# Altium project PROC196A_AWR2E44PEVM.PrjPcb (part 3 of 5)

## Sheet PROC196A_Ethernet_PHY.SchDoc
size 431 x 279 mm; Date: Not shown in title block; ApprovedBy: Not shown in title block; CheckedBy: Not shown in title block; Author: Not shown in title block; CompanyName: Not shown in title block; Engineer: Not shown in title block; Organization: Not shown in title block; Address1: Not shown in title block; Address2: Not shown in title block; Address3: Not shown in title block; Address4: Not shown in title block; DocumentNumber: 12; Revision: Use project parameter SCH_Rev; SheetNumber: 12; SheetTotal: 25; PageSetup: Record=PageOptions¦CenterHorizontal=True¦CenterVertical=True¦PrintScale=1.00¦XCorrection=1.00¦YCorrection=1.00¦PrintKind=0¦BorderSize=5000000¦LeftOffset=0¦BottomOffset=0¦Orientation=2¦PaperLength=1000¦PaperWidth=1000¦Scale=100¦PaperSource=15¦PrintQuality=600¦MediaType=1¦DitherType=10¦PaperKind=Letter¦PrintScaleMode=1
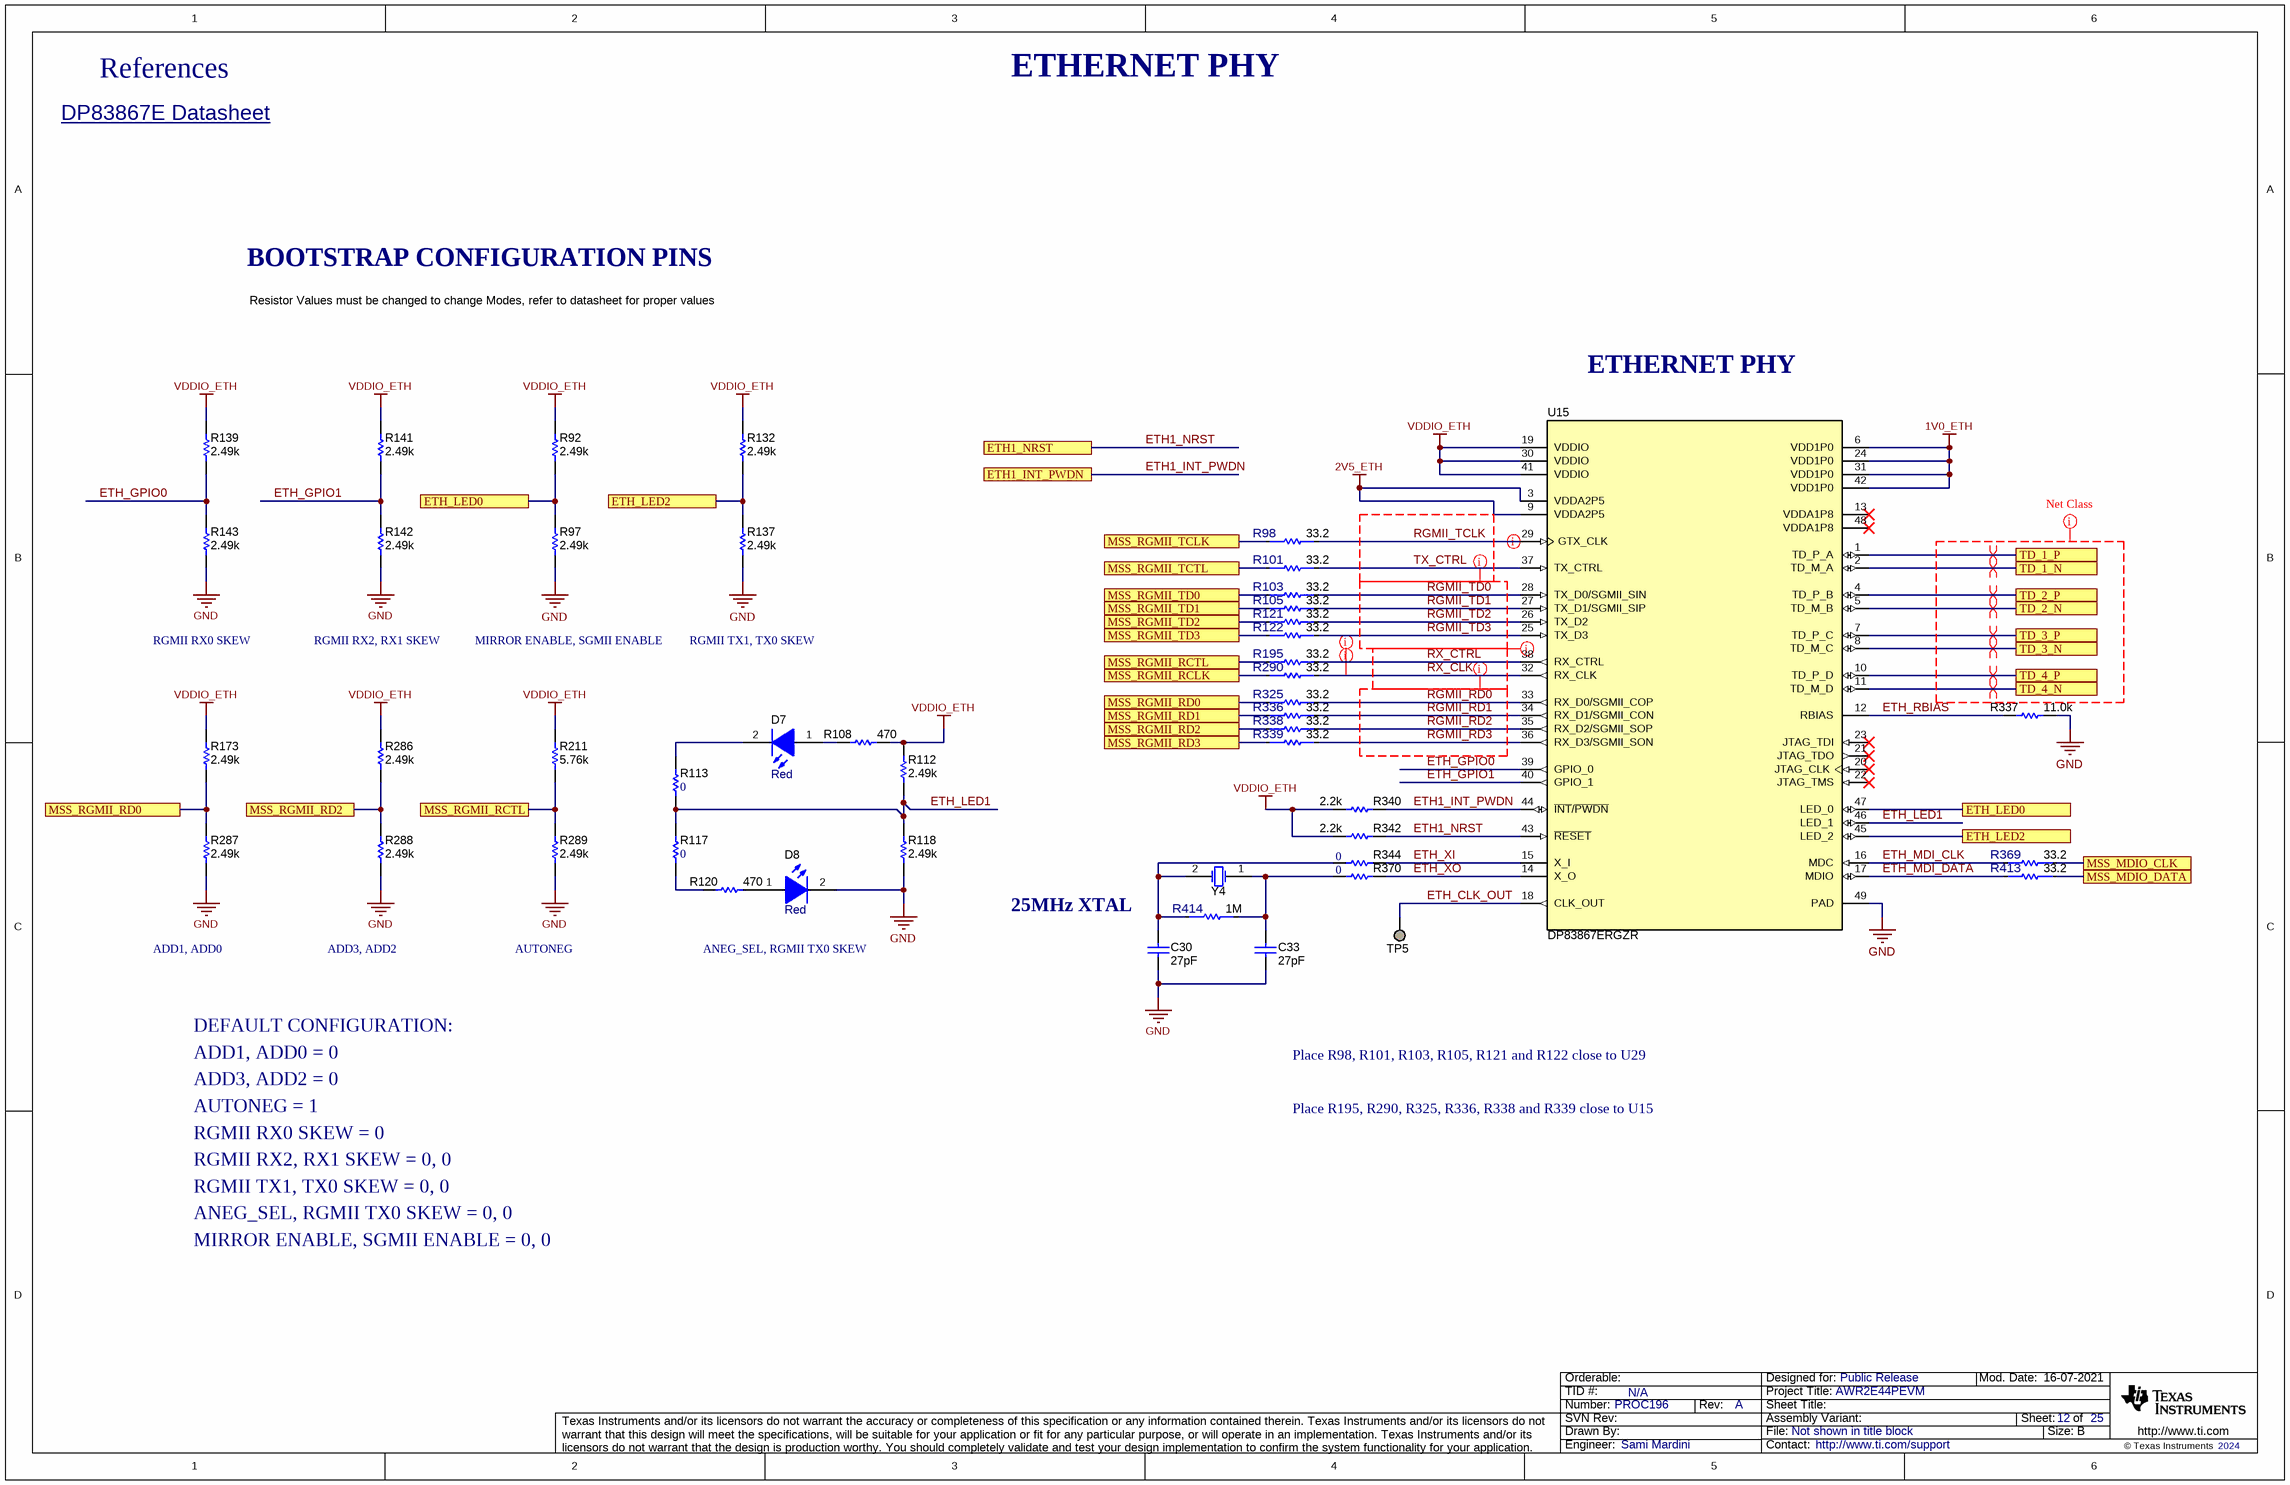
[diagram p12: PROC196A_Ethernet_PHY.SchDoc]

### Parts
C30  ValueDisplayed: 27pF  [0402L]  (hidden comment: GCM1555C1H270JA16D)
C33  ValueDisplayed: 27pF  [0402L]  (hidden comment: GCM1555C1H270JA16D)
D7  value Red  [LS L29K_Red]  (hidden comment: LS L29K-G1J2-1-Z)
D8  value Red  [LS L29K_Red]  (hidden comment: LS L29K-G1J2-1-Z)
R92  ValueDisplayed: 2.49k  [0402L]  (hidden comment: CRCW04022K49FKED)
R97  ValueDisplayed: 2.49k  [0402L]  (hidden comment: CRCW04022K49FKED)
R98  Res_ohm: 33.2  [FP-ERJ-1GNF33R2C_0201-MFG]  (hidden comment: ERJ-1GNF33R2C)
R101  Res_ohm: 33.2  [FP-ERJ-1GNF33R2C_0201-MFG]  (hidden comment: ERJ-1GNF33R2C)
R103  Res_ohm: 33.2  [FP-ERJ-1GNF33R2C_0201-MFG]  (hidden comment: ERJ-1GNF33R2C)
R105  Res_ohm: 33.2  [FP-ERJ-1GNF33R2C_0201-MFG]  (hidden comment: ERJ-1GNF33R2C)
R108  ValueDisplayed: 470  [0402L]  (hidden comment: ERJ-2RKF4700X)
R112  ValueDisplayed: 2.49k  [0402L]  (hidden comment: CRCW04022K49FKED)
R113  ValueDisplayed: 0  [0402L]  (hidden comment: ERJ-2GE0R00X)
R117  ValueDisplayed: 0  [0402L]  (hidden comment: ERJ-2GE0R00X)
R118  ValueDisplayed: 2.49k  [0402L]  (hidden comment: CRCW04022K49FKED)
R120  ValueDisplayed: 470  [0402L]  (hidden comment: ERJ-2RKF4700X)
R121  Res_ohm: 33.2  [FP-ERJ-1GNF33R2C_0201-MFG]  (hidden comment: ERJ-1GNF33R2C)
R122  Res_ohm: 33.2  [FP-ERJ-1GNF33R2C_0201-MFG]  (hidden comment: ERJ-1GNF33R2C)
R132  ValueDisplayed: 2.49k  [0402L]  (hidden comment: CRCW04022K49FKED)
R137  ValueDisplayed: 2.49k  [0402L]  (hidden comment: CRCW04022K49FKED)
R139  ValueDisplayed: 2.49k  [0402L]  (hidden comment: CRCW04022K49FKED)
R141  ValueDisplayed: 2.49k  [0402L]  (hidden comment: CRCW04022K49FKED)
R142  ValueDisplayed: 2.49k  [0402L]  (hidden comment: CRCW04022K49FKED)
R143  ValueDisplayed: 2.49k  [0402L]  (hidden comment: CRCW04022K49FKED)
R173  ValueDisplayed: 2.49k  [0402L]  (hidden comment: CRCW04022K49FKED)
R195  Res_ohm: 33.2  [FP-ERJ-1GNF33R2C_0201-MFG]  (hidden comment: ERJ-1GNF33R2C)
R211  ValueDisplayed: 5.76k  [0402L]  (hidden comment: CRCW04025K76FKED)
R286  ValueDisplayed: 2.49k  [0402L]  (hidden comment: CRCW04022K49FKED)
R287  ValueDisplayed: 2.49k  [0402L]  (hidden comment: CRCW04022K49FKED)
R288  ValueDisplayed: 2.49k  [0402L]  (hidden comment: CRCW04022K49FKED)
R289  ValueDisplayed: 2.49k  [0402L]  (hidden comment: CRCW04022K49FKED)
R290  Res_ohm: 33.2  [FP-ERJ-1GNF33R2C_0201-MFG]  (hidden comment: ERJ-1GNF33R2C)
R325  Res_ohm: 33.2  [FP-ERJ-1GNF33R2C_0201-MFG]  (hidden comment: ERJ-1GNF33R2C)
R336  Res_ohm: 33.2  [FP-ERJ-1GNF33R2C_0201-MFG]  (hidden comment: ERJ-1GNF33R2C)
R337  ValueDisplayed: 11.0k  [0402L]  (hidden comment: CRCW040211K0FKED)
R338  Res_ohm: 33.2  [FP-ERJ-1GNF33R2C_0201-MFG]  (hidden comment: ERJ-1GNF33R2C)
R339  Res_ohm: 33.2  [FP-ERJ-1GNF33R2C_0201-MFG]  (hidden comment: ERJ-1GNF33R2C)
R340  ValueDisplayed: 2.2k  [0402L]  (hidden comment: CRCW04022K20JNED)
R342  ValueDisplayed: 2.2k  [0402L]  (hidden comment: CRCW04022K20JNED)
R344  ValueDisplayed: 0  [0201L]  (hidden comment: CRCW02010000Z0ED)
R369  Res_ohm: 33.2  [FP-ERJ-1GNF33R2C_0201-MFG]  (hidden comment: ERJ-1GNF33R2C)
R370  ValueDisplayed: 0  [0201L]  (hidden comment: CRCW02010000Z0ED)
R413  Res_ohm: 33.2  [FP-ERJ-1GNF33R2C_0201-MFG]  (hidden comment: ERJ-1GNF33R2C)
R414  Res_ohm: 1M  [FP-CRCW06031M00FKEAC_0603-MFG]  (hidden comment: CRCW06031M00FKEAC)
TP5  TESTPOINT  [TP_25MIL-SMT]  (value not drawn)  (no BOM)
U15  DP83867ERGZR  [RGZ0048B]
Y4  ABM3-25.000MHZ-D2Y-T  [XTAL_ABM3]  (value not drawn)

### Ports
ETH1_INT_PWDN, ETH1_NRST, ETH_LED0, ETH_LED2, MSS_MDIO_CLK, MSS_MDIO_DATA, MSS_RGMII_RCLK, MSS_RGMII_RCTL, MSS_RGMII_RD0, MSS_RGMII_RD1, MSS_RGMII_RD2, MSS_RGMII_RD3, MSS_RGMII_TCLK, MSS_RGMII_TCTL, MSS_RGMII_TD0, MSS_RGMII_TD1, MSS_RGMII_TD2, MSS_RGMII_TD3, TD_1_N, TD_1_P, TD_2_N, TD_2_P, TD_3_N, TD_3_P, TD_4_N, TD_4_P

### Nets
1V0_ETH: U15.6(VDD1P0) U15.24(VDD1P0) U15.31(VDD1P0) U15.42(VDD1P0)
2V5_ETH: U15.3(VDDA2P5) U15.9(VDDA2P5)
GND: C30.2 C33.2 D8.2(K) R97.1 R118.1 R137.1 R142.1 R143.1 R287.1 R288.1 R289.1 R337.2 U15.49(PAD)
VDDIO_ETH: R92.2 R108.2 R112.2 R132.2 R139.2 R141.2 R173.2 R211.2 R286.2 R340.2 R342.2 U15.19(VDDIO) U15.30(VDDIO) U15.41(VDDIO)
ETH1_INT_PWDN: R340.1 U15.44(~{INT}/~{PWDN}) ; port ETH1_INT_PWDN
ETH1_NRST: R342.1 U15.43(~{RESET}) ; port ETH1_NRST
ETH_CLK_OUT: TP5.1 U15.18(CLK_OUT)
ETH_GPIO0: R139.1 R143.2 U15.39(GPIO_0)
ETH_GPIO1: R141.1 R142.2 U15.40(GPIO_1)
ETH_LED0: R92.1 R97.2 U15.47(LED_0) ; port ETH_LED0
ETH_LED1: R112.1 R113.1 R117.2 R118.2 U15.46(LED_1)
ETH_LED2: R132.1 R137.2 U15.45(LED_2) ; port ETH_LED2
ETH_MDI_CLK: R369.2 U15.16(MDC)
ETH_MDI_DATA: R413.2 U15.17(MDIO)
ETH_RBIAS: R337.1 U15.12(RBIAS)
ETH_XI: R344.2 U15.15(X_I)
ETH_XO: R370.2 U15.14(X_O)
MSS_MDIO_CLK: R369.1 ; port MSS_MDIO_CLK
MSS_MDIO_DATA: R413.1 ; port MSS_MDIO_DATA
MSS_RGMII_RCLK: R290.1 ; port MSS_RGMII_RCLK
MSS_RGMII_RCTL: R195.1 R211.1 R289.2 ; port MSS_RGMII_RCTL
MSS_RGMII_RD0: R173.1 R287.2 R325.1 ; port MSS_RGMII_RD0
MSS_RGMII_RD1: R336.1 ; port MSS_RGMII_RD1
MSS_RGMII_RD2: R286.1 R288.2 R338.1 ; port MSS_RGMII_RD2
MSS_RGMII_RD3: R339.1 ; port MSS_RGMII_RD3
MSS_RGMII_TCLK: R98.1 ; port MSS_RGMII_TCLK
MSS_RGMII_TCTL: R101.1 ; port MSS_RGMII_TCTL
MSS_RGMII_TD0: R103.1 ; port MSS_RGMII_TD0
MSS_RGMII_TD1: R105.1 ; port MSS_RGMII_TD1
MSS_RGMII_TD2: R121.1 ; port MSS_RGMII_TD2
MSS_RGMII_TD3: R122.1 ; port MSS_RGMII_TD3
RGMII_RD0: R325.2 U15.33(RX_D0/SGMII_COP)
RGMII_RD1: R336.2 U15.34(RX_D1/SGMII_CON)
RGMII_RD2: R338.2 U15.35(RX_D2/SGMII_SOP)
RGMII_RD3: R339.2 U15.36(RX_D3/SGMII_SON)
RGMII_TCLK: R98.2 U15.29(GTX_CLK)
RGMII_TD0: R103.2 U15.28(TX_D0/SGMII_SIN)
RGMII_TD1: R105.2 U15.27(TX_D1/SGMII_SIP)
RGMII_TD2: R121.2 U15.26(TX_D2)
RGMII_TD3: R122.2 U15.25(TX_D3)
RX_CLK: R290.2 U15.32(RX_CLK)
RX_CTRL: R195.2 U15.38(RX_CTRL)
TD_1_N: U15.2(TD_M_A) ; port TD_1_N
TD_1_P: U15.1(TD_P_A) ; port TD_1_P
TD_2_N: U15.5(TD_M_B) ; port TD_2_N
TD_2_P: U15.4(TD_P_B) ; port TD_2_P
TD_3_N: U15.8(TD_M_C) ; port TD_3_N
TD_3_P: U15.7(TD_P_C) ; port TD_3_P
TD_4_N: U15.11(TD_M_D) ; port TD_4_N
TD_4_P: U15.10(TD_P_D) ; port TD_4_P
TX_CTRL: R101.2 U15.37(TX_CTRL)
NetC30_1: C30.1 R344.1 R414.1 Y4.2(OSC2)
NetC33_1: C33.1 R370.1 R414.2 Y4.1(OSC1)
NetD7_1: D7.1(A) R108.1
NetD7_2: D7.2(K) R113.2
NetD8_1: D8.1(A) R120.2
NetR117_1: R117.1 R120.1

Not connected (* = marked no-connect by the designer): U15 13(VDDA1P8)* 20(JTAG_CLK)* 21(JTAG_TDO)* 22(JTAG_TMS)* 23(JTAG_TDI)* 48(VDDA1P8)*

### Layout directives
net class RGMII; net class RGMII_TX_RX: RGMII_RD0, RGMII_RD1, RGMII_RD2, RGMII_RD3, RGMII_TD0, RGMII_TD1, RGMII_TD2, RGMII_TD3
net class RGMII: (no net found under the mark), RX_CLK, RX_CTRL
differential pair: TD_1_N, TD_1_P, TD_2_N, TD_2_P, TD_3_N, TD_3_P, TD_4_N, TD_4_P
net class RGMII_TX_RX: RGMII_TCLK, RGMII_TD0, RGMII_TD1, RGMII_TD2, RGMII_TD3

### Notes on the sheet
- References
- ETHERNET PHY
- DP83867E Datasheet <http://www.ti.com/lit/ds/symlink/dp83867e.pdf>
- BOOTSTRAP CONFIGURATION PINS
- Resistor Values must be changed to change Modes, refer to datasheet for proper values
- RGMII RX0 SKEW
- RGMII RX2, RX1 SKEW
- MIRROR ENABLE, SGMII ENABLE
- RGMII TX1, TX0 SKEW
- ADD1, ADD0
- ADD3, ADD2
- AUTONEG
- ANEG_SEL, RGMII TX0 SKEW
- 25MHz XTAL
- DEFAULT CONFIGURATION:
- ADD1, ADD0 = 0
- ADD3, ADD2 = 0
- Place R98, R101, R103, R105, R121 and R122 close to U29
- AUTONEG = 1
- RGMII RX2, RX1 SKEW = 0, 0
- RGMII RX0 SKEW = 0
- Place R195, R290, R325, R336, R338 and R339 close to U15
- RGMII TX1, TX0 SKEW = 0, 0
- ANEG_SEL, RGMII TX0 SKEW = 0, 0
- MIRROR ENABLE, SGMII ENABLE = 0, 0

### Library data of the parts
C30 C33 = CMP-0860920-1: CAP, CERM, 27 pF, 50 V,+/- 5%, C0G/NP0, AEC-Q200 Grade 1, 0402; Manufacturer: MuRata; AEC Grade: 1; SizeZ_mm: 0.6; U/M: EA; Value: 27pF; SizeY_mm: 0.5; TaMax_C: 125°C; Polarized: N; AEC Qualified: Y; Cap_Case: 0402; AEC Category: Q200; Value2: 50V; SizeAreaWB_mm2: 3; TaMin_C: -55°C
D7 D8 = CMP-0002902-2: LED, Red, SMD; Manufacturer: OSRAM; Tjmax_C: 110°C; Vf_V: 1.8V; Vr_V: 12V; Io_A: 20mA; Angle: 160; Value1: W
R92 R97 R112 R118 R132 R137 R139 R141-R143 R173 R286-R289 = CMP-0026237-2: RES, 2.49 k, 1%, 0.063 W, AEC-Q200 Grade 0, 0402; Manufacturer: Vishay-Dale; Power_W: 63mW; TempCo: 100 ppm/C; Value_Code: 2k49; Value: 2.49k; EIA_Code: E96; SizeX_mm: 1; SizeY_mm: 0.5; SizeZ_mm: 0.6; Value2: 0.063W; AEC Qualified: Y; VDC_V: 50V; AEC Category: Q200; AEC Grade: 0
R98 R101 R103 R105 R121 R122 R195 R290 R325 R336 R338 R339 R369 R413 = CMP-0089575-2: Res Thick Film 0201 33.2 Ohm 1% 0.05W(1/20W) ±200ppm/C Pad SMD Automotive T/R; Manufacturer: Panasonic; TempCo: 200ppm/°C; VDC_V: 25V; AEC Qualified: Yes; SizeZ_mm: 0.26mm; Power_W: 50mW; AEC Grade: Grade 1; Value: 33.2
R108 R120 = CMP-0026699-1: RES, 470, 1%, 0.1 W, AEC-Q200 Grade 0, 0402; Manufacturer: Panasonic; Power_W: 100mW; TempCo: 100 ppm/C; Value_Code: 470R; U/M: EA; Value: 470; SizeX_mm: 1; SizeY_mm: 0.5; SizeZ_mm: 0.6; Value2: 0.1W; AEC Qualified: Y; VDC_V: 50V; AEC Grade: 0; AEC Category: Q200
R113 R117 = CMP-0026992-3: RES, 0, 5%, 0.1 W, AEC-Q200 Grade 0, 0402; Manufacturer: Panasonic; Power_W: 100mW; TempCo: 600 ppm/C; Value_Code: 0000; Value: 0; EIA_Code: E24; SizeX_mm: 1; SizeY_mm: 0.5; SizeZ_mm: 0.6; Value2: 0.1W; CompType: Resistor; AEC Qualified: Y; VDC_V: 50V; AEC Category: Q200; SizeAreaWB_mm2: 3; INSTALLATION: DNP
R211 = CMP-0026468-2: RES, 5.76 k, 1%, 0.063 W, AEC-Q200 Grade 0, 0402; Manufacturer: Vishay-Dale; Power_W: 63mW; TempCo: 100 ppm/C; Value_Code: 5k76; Value: 5.76k; EIA_Code: E96; SizeX_mm: 1; SizeY_mm: 0.5; SizeZ_mm: 0.6; Value2: 0.063W; AEC Qualified: Y; VDC_V: 50V; AEC Category: Q200; AEC Grade: 0
R337 = CMP-0025975-3: RES, 11.0 k, 1%, 0.063 W, AEC-Q200 Grade 0, 0402; Manufacturer: Vishay-Dale; Power_W: 63mW; TempCo: 100 ppm/C; Value_Code: 11k0; Value: 11.0k; EIA_Code: E96; Res_ohm: 11k; SizeX_mm: 1; SizeY_mm: 0.5; SizeZ_mm: 0.6; Value2: 0.063W; AEC Qualified: Y; VDC_V: 50V; AEC Category: Q200; AEC Grade: 0
R340 R342 = CMP-0026890-5: RES, 2.2 k, 5%, 0.063 W, AEC-Q200 Grade 0, 0402; Manufacturer: Vishay-Dale; Power_W: 63mW; TempCo: 200 ppm/C; Value_Code: 2k20; Value: 2.2k; EIA_Code: E24; SizeX_mm: 1; SizeY_mm: 0.5; SizeZ_mm: 0.6; Value2: 0.063W; AEC Qualified: Y; VDC_V: 50V; AEC Category: Q200; AEC Grade: 0
R344 R370 = CMP-0027008-4: RES, 0, 5%, 0.05 W, 0201; Manufacturer: Vishay-Dale; Power_W: 50mW; TempCo: ppm/C; Value_Code: 0000; Value: 0; EIA_Code: E24; SizeX_mm: 0.6; SizeY_mm: 0.3; SizeZ_mm: 0.26; Value2: 0.05W; SizeArea_mm2: 0.18; AEC Qualified: N; AEC Category: Q200
R414 = CMP-0089574-2: Res Thick Film 0603 1M Ohm 1% 1/10W ±100ppm/°C Molded SMD Paper T/R; Manufacturer: Vishay; AEC Qualified: No; Power_W: 100mW; AEC Grade: NA; SizeZ_mm: 0.55mm; VDC_V: 75V
TP5 = CMP-0078143-3: TEST POINT.  No entry in BOM.
U15 = CMP-0076013-2: Extended Temperature Gigabit Ethernet PHY with SGMII, RGZ0048B (VQFN-48); Manufacturer: Texas Instruments; Alternate PartNumber: DP83867ERGZT; SizeX_mm: 7; CompType: IC; SizeZ_mm: 1; SizeArea_mm2: 49; SizeAreaWB_mm2: 81; U/M: EA
Y4 = CMP-0004620-3: Crystal, 25 MHz, 18 pF, SMD; Manufacturer: Abracon Corporation; TaMin_C: -40°C; Frequency Stability: +/-30ppm; Frequency_Fixed: 25MHz; TaMax_C: 85°C

## Sheet PROC196A_Ethernet_Magnetics.SchDoc
size 431 x 279 mm; Date: Not shown in title block; ApprovedBy: Not shown in title block; CheckedBy: Not shown in title block; Author: Not shown in title block; CompanyName: Not shown in title block; Engineer: Not shown in title block; Organization: Not shown in title block; Address1: Not shown in title block; Address2: Not shown in title block; Address3: Not shown in title block; Address4: Not shown in title block; DocumentNumber: 13; Revision: Use project parameter SCH_Rev; SheetNumber: 13; SheetTotal: 25; PageSetup: Record=PageOptions¦CenterHorizontal=True¦CenterVertical=True¦PrintScale=1.00¦XCorrection=1.00¦YCorrection=1.00¦PrintKind=0¦BorderSize=5000000¦LeftOffset=0¦BottomOffset=0¦Orientation=2¦PaperLength=1000¦PaperWidth=1000¦Scale=100¦PaperSource=15¦PrintQuality=600¦MediaType=1¦DitherType=10¦PaperKind=Letter¦PrintScaleMode=1
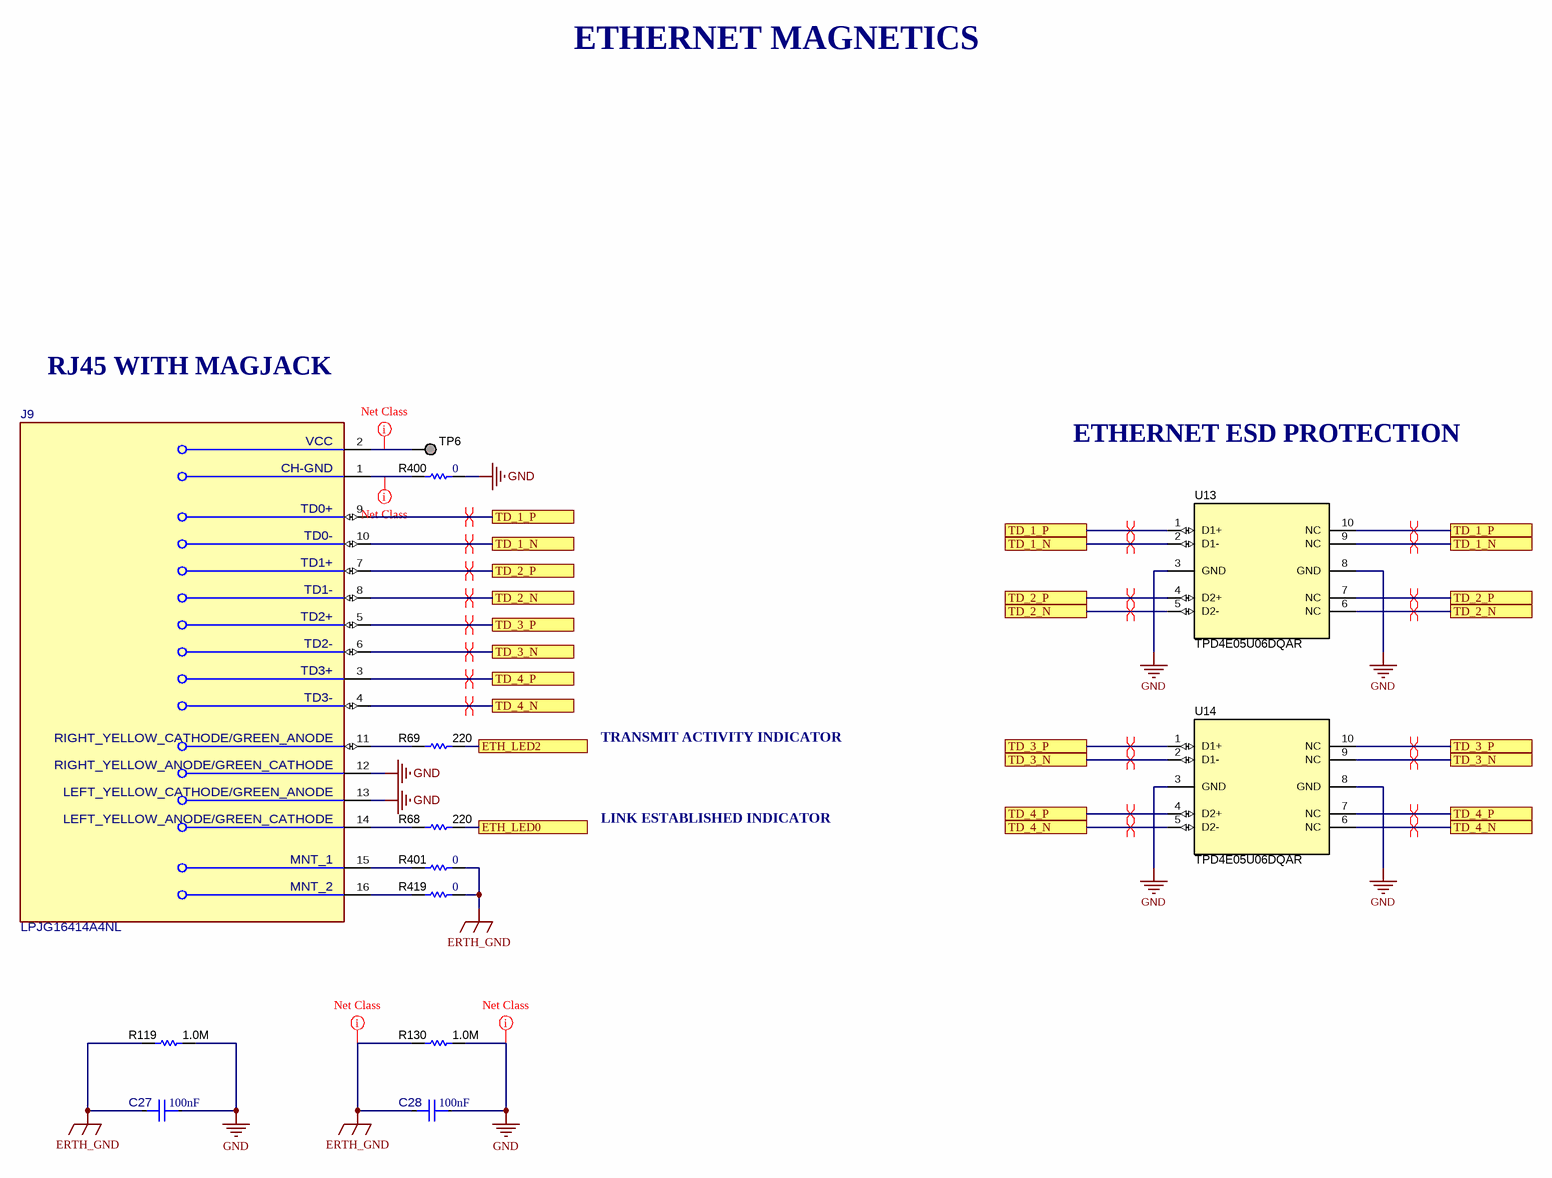
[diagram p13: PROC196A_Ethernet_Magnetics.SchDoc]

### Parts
C27  Cap_F: 100nF  [FP-C0603C104K4RACAUTO_0603-MFG]  (hidden comment: C0603C104K4RACAUTO)
C28  Cap_F: 100nF  [FP-C0603C104K4RACAUTO_0603-MFG]  (hidden comment: C0603C104K4RACAUTO)
J9  LPJG16414A4NL  [FP-LPJG16414A4NL_CONN_RJ45-MFG]
R68  ValueDisplayed: 220  [0402L]  (hidden comment: CRCW0402220RJNED)
R69  ValueDisplayed: 220  [0402L]  (hidden comment: CRCW0402220RJNED)
R119  ValueDisplayed: 1.0M  [1206L]  (hidden comment: CRCW12061M00JNEA)
R130  ValueDisplayed: 1.0M  [1206L]  (hidden comment: CRCW12061M00JNEA)
R400  ValueDisplayed: 0  [0402L]  (hidden comment: ERJ-2GE0R00X)
R401  ValueDisplayed: 0  [0402L]  (hidden comment: ERJ-2GE0R00X)
R419  ValueDisplayed: 0  [0402L]  (hidden comment: ERJ-2GE0R00X)
TP6  TESTPOINT  [TP_25MIL-SMT]  (value not drawn)  (no BOM)
U13  TPD4E05U06DQAR  [DQA0010A]
U14  TPD4E05U06DQAR  [DQA0010A]

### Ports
ETH_LED0, ETH_LED2, TD_1_N, TD_1_P, TD_2_N, TD_2_P, TD_3_N, TD_3_P, TD_4_N, TD_4_P

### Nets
ERTH_GND: C27.2 C28.2 R119.1 R130.1 R401.2 R419.2
GND: C27.1 C28.1 J9.12(RIGHT_YELLOW_ANODE/GREEN_CATHODE) J9.13(LEFT_YELLOW_CATHODE/GREEN_ANODE) R119.2 R130.2 R400.2 U13.3(GND) U13.8(GND) U14.3(GND) U14.8(GND)
ETH_LED0: R68.1 ; port ETH_LED0
ETH_LED2: R69.2 ; port ETH_LED2
TD_1_N: J9.10(TD0-) U13.2(D1-) U13.9(NC) ; port TD_1_N
TD_1_P: J9.9(TD0+) U13.1(D1+) U13.10(NC) ; port TD_1_P
TD_2_N: J9.8(TD1-) U13.5(D2-) U13.6(NC) ; port TD_2_N
TD_2_P: J9.7(TD1+) U13.4(D2+) U13.7(NC) ; port TD_2_P
TD_3_N: J9.6(TD2-) U14.2(D1-) U14.9(NC) ; port TD_3_N
TD_3_P: J9.5(TD2+) U14.1(D1+) U14.10(NC) ; port TD_3_P
TD_4_N: J9.4(TD3-) U14.5(D2-) U14.6(NC) ; port TD_4_N
TD_4_P: J9.3(TD3+) U14.4(D2+) U14.7(NC) ; port TD_4_P
NetJ9_1: J9.1(CH-GND) R400.1
NetJ9_2: J9.2(VCC) TP6.1
NetJ9_11: J9.11(RIGHT_YELLOW_CATHODE/GREEN_ANODE) R69.1
NetJ9_14: J9.14(LEFT_YELLOW_ANODE/GREEN_CATHODE) R68.2
NetJ9_15: J9.15(MNT_1) R401.1
NetJ9_16: J9.16(MNT_2) R419.1

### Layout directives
differential pair: TD_1_N, TD_1_P, TD_2_N, TD_2_P, TD_3_N, TD_3_P, TD_4_N, TD_4_P
net class PWR: ERTH_GND, GND, NetJ9_1, NetJ9_2

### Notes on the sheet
- ETHERNET MAGNETICS
- RJ45 WITH MAGJACK
- ETHERNET ESD PROTECTION
- TRANSMIT ACTIVITY INDICATOR
- LINK ESTABLISHED INDICATOR

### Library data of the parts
C27 C28 = CMP-0089508-1: C0603 0.10 μF X7R 30ppm/°C 10.00% 16 V; Manufacturer: KEMET; AEC Qualified: Yes; Tolerance_%: 0.1%; VDC_V: 16V; ValueDisplayed: 0.10 μF; AEC Grade: Grade 1; SizeZ_mm: 0.87mm
J9 = CMP-0088394-1: RJ45 Connector with 1000 Base-TX Inetgrated Magnetic; Manufacturer: LINK-PP; DUT-Pitch_mm: 1.27mm; Conn Orientation: Horizontal; ContactFinish: Gold; Conn Gender: Female; Is Female: yes; AEC Qualified: No; Shrouded: true
R68 R69 = CMP-0026878-3: RES, 220, 5%, 0.063 W, AEC-Q200 Grade 0, 0402; Manufacturer: Vishay-Dale; Power_W: 63mW; TempCo: 200 ppm/C; Value_Code: 220R; Value: 220; EIA_Code: E24; SizeX_mm: 1; SizeY_mm: 0.5; SizeZ_mm: 0.6; Value2: 0.063W; AEC Qualified: Y; VDC_V: 50V; AEC Category: Q200; AEC Grade: 0
R119 R130 = CMP-0018610-3: RES, 1.0 M, 5%, 0.25 W, AEC-Q200 Grade 0, 1206; Manufacturer: Vishay-Dale; Power_W: 250mW; TempCo: 200 ppm/C; Value_Code: 1M00; Value: 1.0Meg; EIA_Code: E24; Res_ohm: 1M; SizeX_mm: 3.2; SizeY_mm: 1.6; SizeZ_mm: 1.35; Value2: 0.25W; SizeArea_mm2: 5.12; AEC Qualified: Y; VDC_V: 200V; AEC Category: Q200; AEC Grade: 0
R400 R401 R419 = CMP-0026992-3: as R113 on sheet PROC196A_Ethernet_PHY
TP6 = CMP-0078143-3: TEST POINT.  No entry in BOM.
U13 U14 = CMP-0073613-3: 4-Channel Ultra-Low-Capacitance IEC ESD Protection Diode, DQA0010A (USON-10); Alternate Manufacturer: Texas Instruments; Green_Lifecycle: Active; SizeAreaWB_mm2: 7.0; Green_REACh: Passed; SizeZ_mm: 0.55; SizeX_mm: 1.0; SizeY_mm: 2.5; CompType: IC; AEC Category: Q200; AEC Qualified: N

## Sheet PROC196A_Auto_Ethernet_PHY.SchDoc
size 431 x 279 mm; Date: Not shown in title block; ApprovedBy: Not shown in title block; CheckedBy: Not shown in title block; Author: Not shown in title block; CompanyName: Not shown in title block; Engineer: Not shown in title block; Organization: Not shown in title block; Address1: Not shown in title block; Address2: Not shown in title block; Address3: Not shown in title block; Address4: Not shown in title block; DocumentNumber: 14; Revision: Use project parameter SCH_Rev; SheetNumber: 14; SheetTotal: 25; PageSetup: Record=PageOptions¦CenterHorizontal=True¦CenterVertical=True¦PrintScale=1.00¦XCorrection=1.00¦YCorrection=1.00¦PrintKind=0¦BorderSize=5000000¦LeftOffset=0¦BottomOffset=0¦Orientation=2¦PaperLength=1000¦PaperWidth=1000¦Scale=100¦PaperSource=15¦PrintQuality=600¦MediaType=1¦DitherType=10¦PaperKind=Letter¦PrintScaleMode=1
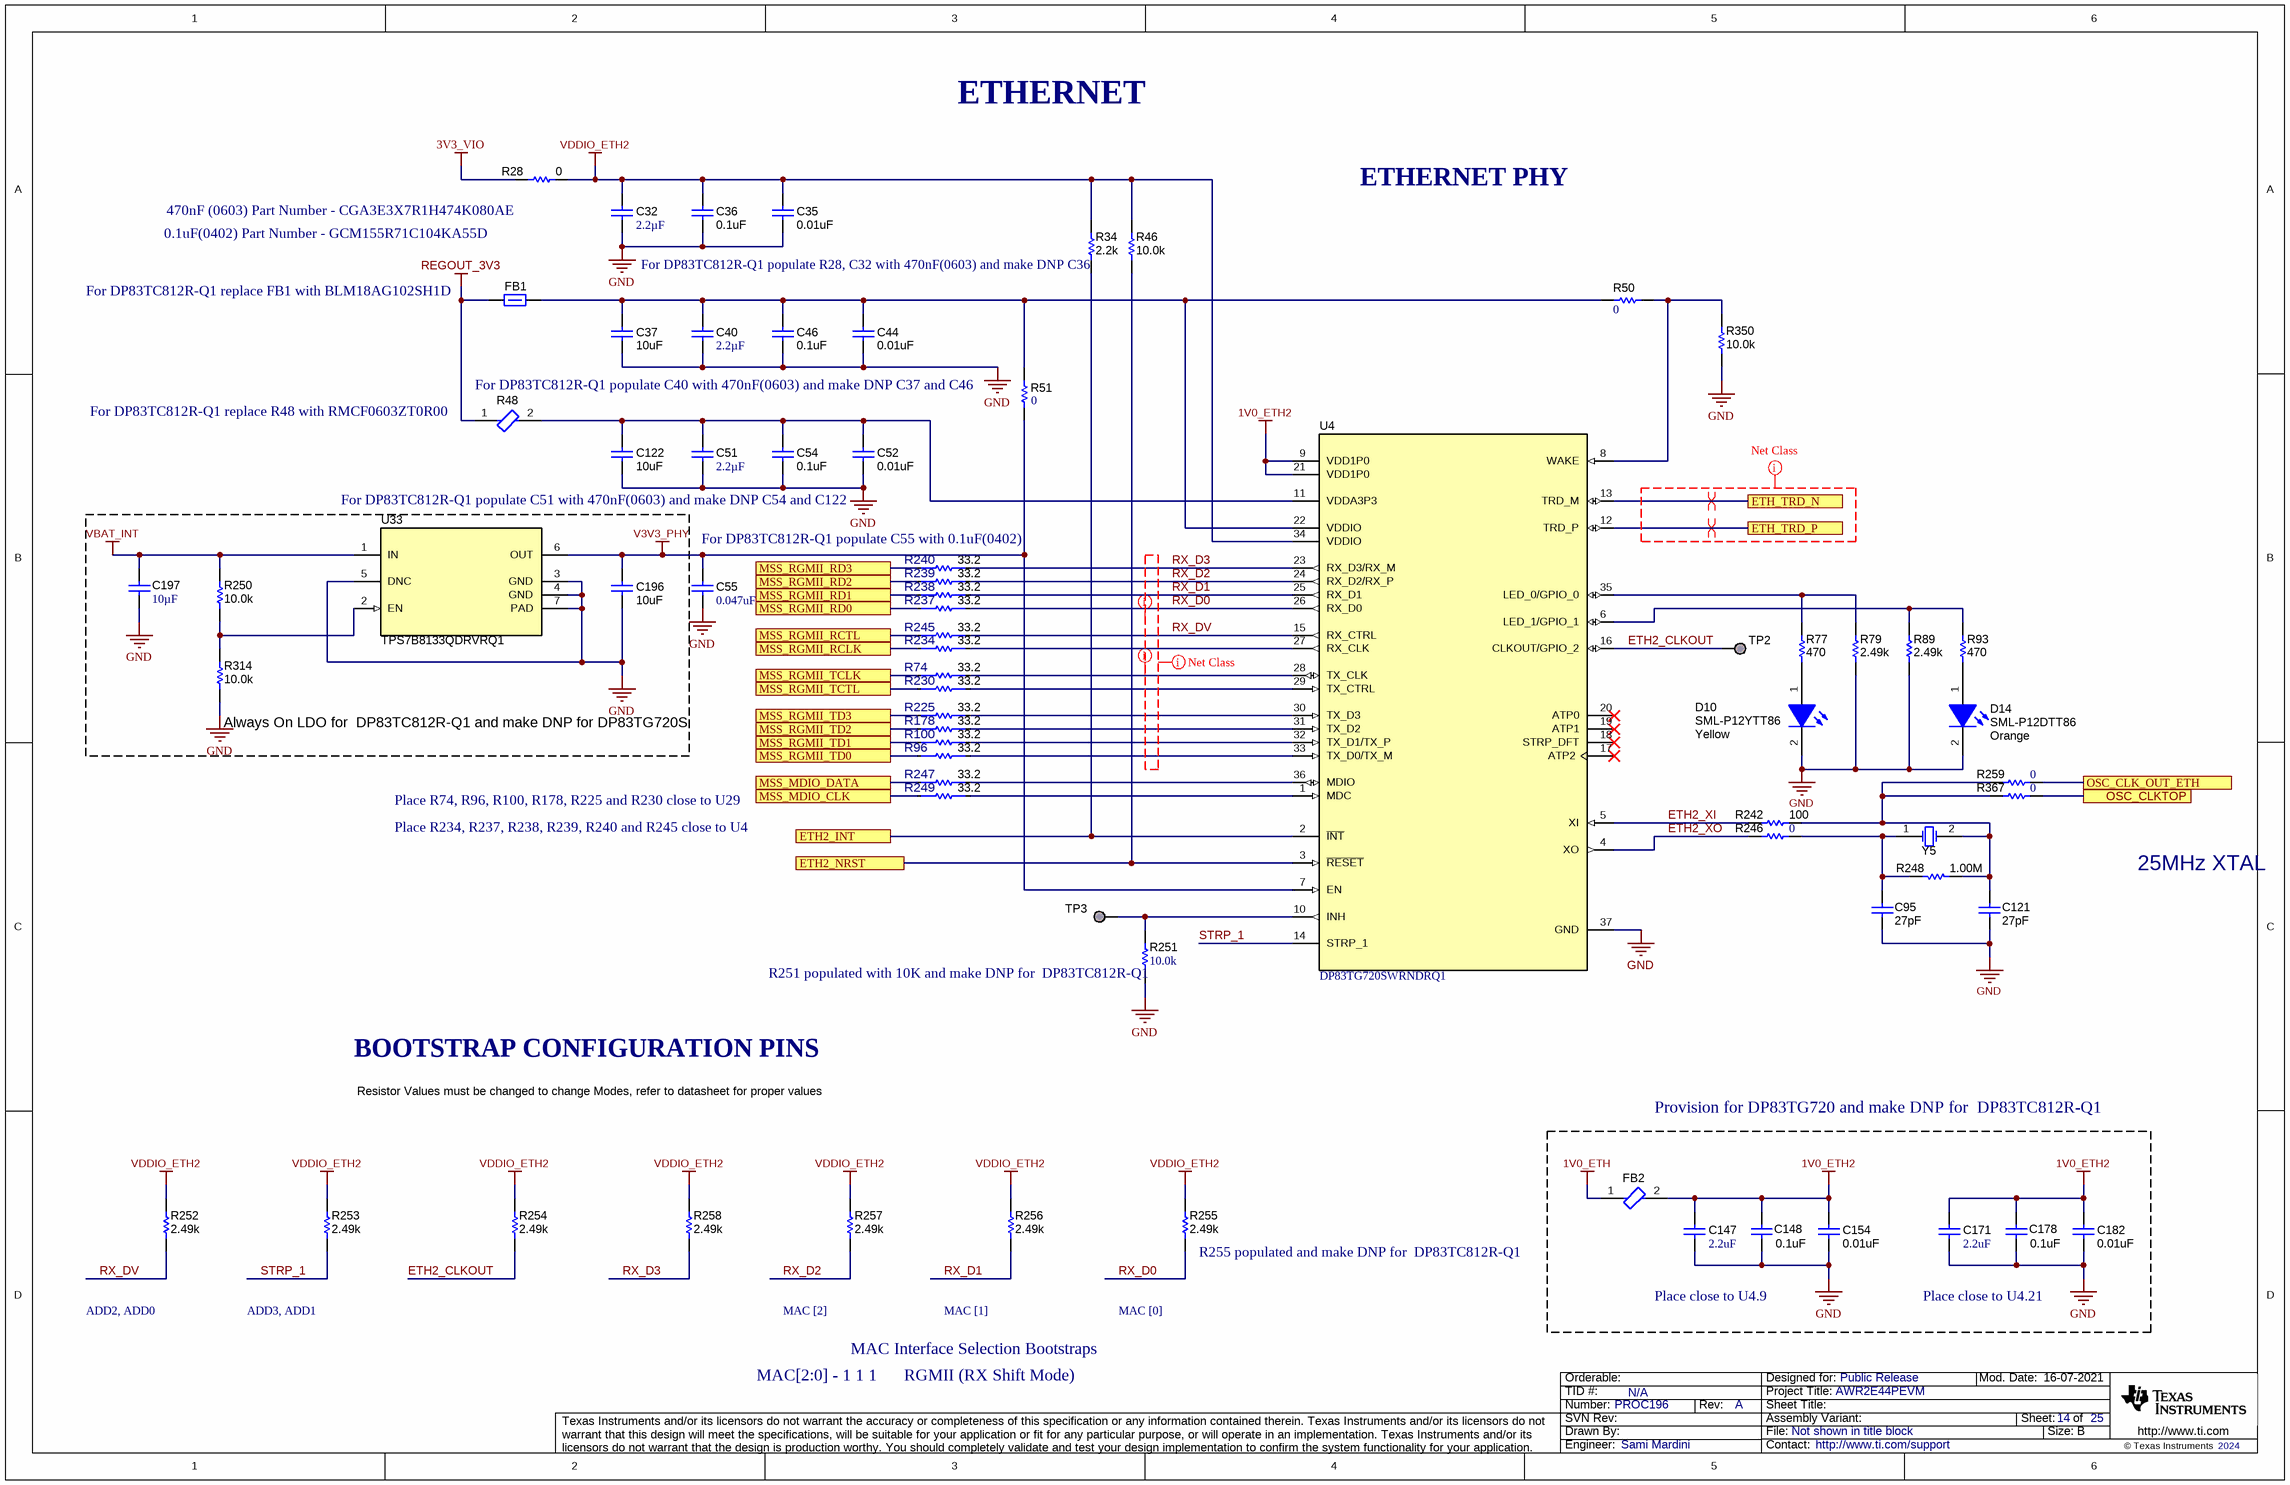
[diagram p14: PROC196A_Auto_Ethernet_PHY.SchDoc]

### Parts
C32  Cap_F: 2.2µF  [0603L]  (hidden comment: GCM188R70J225KE22D)
C35  ValueDisplayed: 0.01uF  [0402L]  (hidden comment: CGA2B3X7R1H103K050BB)
C36  ValueDisplayed: 0.1uF  [0402L]  (hidden comment: GCM155R71C104KA55D)
C37  ValueDisplayed: 10uF  [0805L]  (hidden comment: GCM21BR71A106KE22L)
C40  Cap_F: 2.2µF  [0603L]  (hidden comment: GCM188R70J225KE22D)
C44  ValueDisplayed: 0.01uF  [0402L]  (hidden comment: CGA2B3X7R1H103K050BB)
C46  ValueDisplayed: 0.1uF  [0402L]  (hidden comment: GCM155R71C104KA55D)
C51  Cap_F: 2.2µF  [0603L]  (hidden comment: GCM188R70J225KE22D)
C52  ValueDisplayed: 0.01uF  [0402L]  (hidden comment: CGA2B3X7R1H103K050BB)
C54  ValueDisplayed: 0.1uF  [0402L]  (hidden comment: GCM155R71C104KA55D)
C55  ValueDisplayed: 0.047uF  [0402L]  (hidden comment: GRM155R71E473KA88D)
C95  ValueDisplayed: 27pF  [0402L]  (hidden comment: GCM1555C1H270JA16D)
C121  ValueDisplayed: 27pF  [0402L]  (hidden comment: GCM1555C1H270JA16D)
C122  ValueDisplayed: 10uF  [0805L]  (hidden comment: GCM21BR71A106KE22L)
C147  ValueDisplayed: 2.2uF  [0603L]  (hidden comment: GCM188R70J225KE22D)
C148  ValueDisplayed: 0.1uF  [0402L]  (hidden comment: GCM155R71A104KA55D)
C154  ValueDisplayed: 0.01uF  [0402L]  (hidden comment: CGA2B3X7R1H103K050BB)
C171  ValueDisplayed: 2.2uF  [0603L]  (hidden comment: GCM188R70J225KE22D)
C178  ValueDisplayed: 0.1uF  [0402L]  (hidden comment: GCM155R71A104KA55D)
C182  ValueDisplayed: 0.01uF  [0402L]  (hidden comment: CGA2B3X7R1H103K050BB)
C196  ValueDisplayed: 10uF  [0805L]  (hidden comment: GCM21BR71A106KE22L)
C197  ValueDisplayed: 10µF  [1206L]  (hidden comment: CGA5L1X7R1H106K160AE)
D10  SML-P12YTT86  value Yellow  [LED_SMLP12_YELLOW]
D14  SML-P12DTT86  value Orange  [LED_SMLP12_ORANGE]
FB1  BLM18HE102SN1D  [0603]  (value not drawn)
FB2  BLM18KG601SH1  [FP-BLM18KG601SH1_0603 (1608 Metric)-MFG]  (value not drawn)
R28  ValueDisplayed: 0  [0603L]  (hidden comment: RMCF0603ZT0R00)
R34  ValueDisplayed: 2.2k  [0402L]  (hidden comment: CRCW04022K20JNED)
R46  ValueDisplayed: 10.0k  [0402L]  (hidden comment: CRCW040210K0FKED)
R48  BLM18KG601SH1  [FP-BLM18KG601SH1_0603 (1608 Metric)-MFG]  (value not drawn)
R50  ValueDisplayed: 0  [0402L]  (hidden comment: ERJ-2GE0R00X)
R51  ValueDisplayed: 0  [0402L]  (hidden comment: ERJ-2GE0R00X)
R74  Res_ohm: 33.2  [FP-ERJ-1GNF33R2C_0201-MFG]  (hidden comment: ERJ-1GNF33R2C)
R77  ValueDisplayed: 470  [0402L]  (hidden comment: ERJ-2RKF4700X)
R79  ValueDisplayed: 2.49k  [0402L]  (hidden comment: CRCW04022K49FKED)
R89  ValueDisplayed: 2.49k  [0402L]  (hidden comment: CRCW04022K49FKED)
R93  ValueDisplayed: 470  [0402L]  (hidden comment: ERJ-2RKF4700X)
R96  Res_ohm: 33.2  [FP-ERJ-1GNF33R2C_0201-MFG]  (hidden comment: ERJ-1GNF33R2C)
R100  Res_ohm: 33.2  [FP-ERJ-1GNF33R2C_0201-MFG]  (hidden comment: ERJ-1GNF33R2C)
R178  Res_ohm: 33.2  [FP-ERJ-1GNF33R2C_0201-MFG]  (hidden comment: ERJ-1GNF33R2C)
R225  Res_ohm: 33.2  [FP-ERJ-1GNF33R2C_0201-MFG]  (hidden comment: ERJ-1GNF33R2C)
R230  Res_ohm: 33.2  [FP-ERJ-1GNF33R2C_0201-MFG]  (hidden comment: ERJ-1GNF33R2C)
R234  Res_ohm: 33.2  [FP-ERJ-1GNF33R2C_0201-MFG]  (hidden comment: ERJ-1GNF33R2C)
R237  Res_ohm: 33.2  [FP-ERJ-1GNF33R2C_0201-MFG]  (hidden comment: ERJ-1GNF33R2C)
R238  Res_ohm: 33.2  [FP-ERJ-1GNF33R2C_0201-MFG]  (hidden comment: ERJ-1GNF33R2C)
R239  Res_ohm: 33.2  [FP-ERJ-1GNF33R2C_0201-MFG]  (hidden comment: ERJ-1GNF33R2C)
R240  Res_ohm: 33.2  [FP-ERJ-1GNF33R2C_0201-MFG]  (hidden comment: ERJ-1GNF33R2C)
R242  ValueDisplayed: 100  [0402L]  (hidden comment: ERJ-2GEJ101X)
R245  Res_ohm: 33.2  [FP-ERJ-1GNF33R2C_0201-MFG]  (hidden comment: ERJ-1GNF33R2C)
R246  ValueDisplayed: 0  [0402L]  (hidden comment: ERJ-2GE0R00X)
R247  Res_ohm: 33.2  [FP-ERJ-1GNF33R2C_0201-MFG]  (hidden comment: ERJ-1GNF33R2C)
R248  ValueDisplayed: 1.00M  [0603L]  (hidden comment: CRCW06031M00FKEA)
R249  Res_ohm: 33.2  [FP-ERJ-1GNF33R2C_0201-MFG]  (hidden comment: ERJ-1GNF33R2C)
R250  ValueDisplayed: 10.0k  [0402L]  (hidden comment: CRCW040210K0FKED)
R251  ValueDisplayed: 10.0k  [0402L]  (hidden comment: CRCW040210K0FKED)
R252  ValueDisplayed: 2.49k  [0402L]  (hidden comment: CRCW04022K49FKED)
R253  ValueDisplayed: 2.49k  [0402L]  (hidden comment: CRCW04022K49FKED)
R254  ValueDisplayed: 2.49k  [0402L]  (hidden comment: CRCW04022K49FKED)
R255  ValueDisplayed: 2.49k  [0402L]  (hidden comment: CRCW04022K49FKED)
R256  ValueDisplayed: 2.49k  [0402L]  (hidden comment: CRCW04022K49FKED)
R257  ValueDisplayed: 2.49k  [0402L]  (hidden comment: CRCW04022K49FKED)
R258  ValueDisplayed: 2.49k  [0402L]  (hidden comment: CRCW04022K49FKED)
R259  ValueDisplayed: 0  [0402L]  (hidden comment: ERJ-2GE0R00X)
R314  ValueDisplayed: 10.0k  [0402L]  (hidden comment: CRCW040210K0FKED)
R350  ValueDisplayed: 10.0k  [0402L]  (hidden comment: CRCW040210K0FKED)
R367  ValueDisplayed: 0  [0402L]  (hidden comment: ERJ-2GE0R00X)
TP2  TESTPOINT  [TP_25MIL-SMT]  (value not drawn)  (no BOM)
TP3  TESTPOINT  [TP_25MIL-SMT]  (value not drawn)  (no BOM)
U4  DP83TG720SWRNDRQ1  [RND0036A]
U33  TPS7B8133QDRVRQ1  [DRV0006A]
Y5  ABM3-25.000MHZ-D2W-T  [XTAL_ABM3]  (value not drawn)

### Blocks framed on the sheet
Always On LDO for  DP83TC812R-Q1 and make DNP for DP83TG720S: C196 C197 R250 R314 U33
Provision for DP83TG720 and make DNP for  DP83TC812R-Q1: C147 C148 C154 C171 C178 C182 FB2

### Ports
ETH2_INT, ETH2_NRST, ETH_TRD_N, ETH_TRD_P, MSS_MDIO_CLK, MSS_MDIO_DATA, MSS_RGMII_RCLK, MSS_RGMII_RCTL, MSS_RGMII_RD0, MSS_RGMII_RD1, MSS_RGMII_RD2, MSS_RGMII_RD3, MSS_RGMII_TCLK, MSS_RGMII_TCTL, MSS_RGMII_TD0, MSS_RGMII_TD1, MSS_RGMII_TD2, MSS_RGMII_TD3, OSC_CLK_OUT_ETH, OSC_CLKTOP

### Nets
1V0_ETH: FB2.1
1V0_ETH2: C147.1 C148.1 C154.1 C171.1 C178.1 C182.1 FB2.2 U4.9(VDD1P0) U4.21(VDD1P0)
3V3_VIO: R28.1
GND: C32.2 C35.2 C36.1 C37.2 C40.2 C44.2 C46.1 C51.2 C52.2 C54.1 C55.1 C95.2 C121.2 C122.2 C147.2 C148.2 C154.2 C171.2 C178.2 C182.2 C196.2 C197.2 D10.2(K) D14.2(K) R79.1 R89.2 R251.1 R314.1 R350.2 U4.37(GND) U33.3(GND) U33.4(GND) U33.5(DNC) U33.7(PAD)
REGOUT_3V3: FB1.1 R48.1
V3V3_PHY: C55.2 C196.1 R51.1 U4.7(EN) U33.6(OUT)
VBAT_INT: C197.1 R250.2 U33.1(IN)
VDDIO_ETH2: C32.1 C35.1 C36.2 R28.2 R34.1 R46.1 R252.2 R253.2 R254.2 R255.2 R256.2 R257.2 R258.2 U4.34(VDDIO)
ETH2_CLKOUT: R254.1 TP2.1 U4.16(CLKOUT/GPIO_2)
ETH2_INT: R34.2 U4.2(~{INT}) ; port ETH2_INT
ETH2_NRST: R46.2 U4.3(~{RESET}) ; port ETH2_NRST
ETH2_XI: R242.1 U4.5(XI)
ETH2_XO: R246.2 U4.4(XO)
ETH_TRD_N: U4.13(TRD_M) ; port ETH_TRD_N
ETH_TRD_P: U4.12(TRD_P) ; port ETH_TRD_P
MSS_MDIO_CLK: R249.1 ; port MSS_MDIO_CLK
MSS_MDIO_DATA: R247.1 ; port MSS_MDIO_DATA
MSS_RGMII_RCLK: R234.1 ; port MSS_RGMII_RCLK
MSS_RGMII_RCTL: R245.1 ; port MSS_RGMII_RCTL
MSS_RGMII_RD0: R237.1 ; port MSS_RGMII_RD0
MSS_RGMII_RD1: R238.1 ; port MSS_RGMII_RD1
MSS_RGMII_RD2: R239.1 ; port MSS_RGMII_RD2
MSS_RGMII_RD3: R240.1 ; port MSS_RGMII_RD3
MSS_RGMII_TCLK: R74.1 ; port MSS_RGMII_TCLK
MSS_RGMII_TCTL: R230.1 ; port MSS_RGMII_TCTL
MSS_RGMII_TD0: R96.1 ; port MSS_RGMII_TD0
MSS_RGMII_TD1: R100.1 ; port MSS_RGMII_TD1
MSS_RGMII_TD2: R178.1 ; port MSS_RGMII_TD2
MSS_RGMII_TD3: R225.1 ; port MSS_RGMII_TD3
OSC_CLK_OUT_ETH: R259.1 ; port OSC_CLK_OUT_ETH
OSC_CLKTOP: R367.1 ; port OSC_CLKTOP
RX_D0: R237.2 R255.1 U4.26(RX_D0)
RX_D1: R238.2 R256.1 U4.25(RX_D1)
RX_D2: R239.2 R257.1 U4.24(RX_D2/RX_P)
RX_D3: R240.2 R258.1 U4.23(RX_D3/RX_M)
RX_DV: R245.2 R252.1 U4.15(RX_CTRL)
STRP_1: R253.1 U4.14(STRP_1)
NetC37_1: C37.1 C40.1 C44.1 C46.2 FB1.2 R50.2 R51.2 U4.22(VDDIO)
NetC51_1: C51.1 C52.1 C54.2 C122.1 R48.2 U4.11(VDDA3P3)
NetC95_1: C95.1 R246.1 R248.2 Y5.1(OSC1)
NetC121_1: C121.1 R242.2 R248.1 R259.2 R367.2 Y5.2(OSC2)
NetD10_1: D10.1(A) R77.1
NetD14_1: D14.1(A) R93.1
NetR50_1: R50.1 R350.1 U4.8(WAKE)
NetR74_2: R74.2 U4.28(TX_CLK)
NetR77_2: R77.2 R79.2 U4.35(LED_0/GPIO_0)
NetR89_1: R89.1 R93.2 U4.6(LED_1/GPIO_1)
NetR96_2: R96.2 U4.33(TX_D0/TX_M)
NetR100_2: R100.2 U4.32(TX_D1/TX_P)
NetR178_2: R178.2 U4.31(TX_D2)
NetR225_2: R225.2 U4.30(TX_D3)
NetR230_2: R230.2 U4.29(TX_CTRL)
NetR234_2: R234.2 U4.27(RX_CLK)
NetR247_2: R247.2 U4.36(MDIO)
NetR249_2: R249.2 U4.1(MDC)
NetR250_1: R250.1 R314.2 U33.2(EN)
NetR251_2: R251.2 TP3.1 U4.10(INH)

Not connected (* = marked no-connect by the designer): U4 17(ATP2)* 18(STRP_DFT)* 19(ATP1)* 20(ATP0)*

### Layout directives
net class RGMII: (no net found under the mark), NetR74_2
differential pair: ETH_TRD_N, ETH_TRD_P

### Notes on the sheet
- ETHERNET
- (near R28) 470nF (0603) Part Number - CGA3E3X7R1H474K080AE
- ETHERNET PHY
- For DP83TC812R-Q1 replace FB1 with BLM18AG102SH1D
- 0.1uF(0402) Part Number - GCM155R71C104KA55D
- (near R34) For DP83TC812R-Q1 populate R28, C32 with 470nF(0603) and make DNP C36
- For DP83TC812R-Q1 replace R48 with RMCF0603ZT0R00
- For DP83TC812R-Q1 populate C40 with 470nF(0603) and make DNP C37 and C46
- For DP83TC812R-Q1 populate C51 with 470nF(0603) and make DNP C54 and C122
- For DP83TC812R-Q1 populate C55 with 0.1uF(0402)
- Place R74, R96, R100, R178, R225 and R230 close to U29
- Place R234, R237, R238, R239, R240 and R245 close to U4
- 25MHz XTAL
- (near R251) R251 populated with 10K and make DNP for  DP83TC812R-Q1
- BOOTSTRAP CONFIGURATION PINS
- Resistor Values must be changed to change Modes, refer to datasheet for proper values
- (near R255) R255 populated and make DNP for  DP83TC812R-Q1
- Place close to U4.9
- Place close to U4.21
- ADD2, ADD0
- ADD3, ADD1
- MAC [2]
- MAC Interface Selection Bootstraps
- MAC [1]
- MAC [0]
- MAC[2:0] - 1 1 1      RGMII (RX Shift Mode)

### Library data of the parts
C32 C40 C51 = CMP-0007134-5: CAP, CERM, 2.2 uF, 6.3 V, +/- 10%, X7R, AEC-Q200 Grade 1, 0603; Manufacturer: MuRata; TaMin_C: -55°C; Polarized: N; SizeAreaWB_mm2: 4.68; Value1: Unknown; U/M: EA; Value: 2.2uF; TaMax_C: 125°C; SizeZ_mm: 1; SizeX_mm: 1.6; SizeY_mm: 0.8; Cap_Case: 0603; Value2: 6.3V; SizeArea_mm2: 1.28; AEC Qualified: Y; AEC Category: Q200
C35 C44 C52 C154 C182 = CMP-0006324-2: CAP, CERM, 0.01 uF, 50 V, +/- 10%, X7R, AEC-Q200 Grade 1, 0402; Manufacturer: TDK; TaMin_C: -55°C; ESR_ohm: 0.333065; Polarized: N; SizeAreaWB_mm2: 3; Value1: 0.333065 ohm; U/M: EA; Value: 0.01uF; TaMax_C: 125°C; SizeZ_mm: 0.6; SizeX_mm: 1; SizeY_mm: 0.5; Cap_Case: 0402; Value2: 50V; CompType: Capacitor; AEC Qualified: Y; Cap_F: 10nF; IRMS_A: 323.373mA; AEC Category: Q200
C36 C46 C54 = CMP-0006351-2: CAP, CERM, 0.1 uF, 16 V, +/- 10%, X7R, 0402; Manufacturer: MuRata; TaMin_C: -55°C; Polarized: N; SizeAreaWB_mm2: 3; Value1: Unknown; U/M: EA; Value: 0.1uF; TaMax_C: 125°C; SizeZ_mm: 0.6; SizeX_mm: 1; SizeY_mm: 0.5; Cap_Case: 0402; Value2: 16V; CompType: Capacitor; Cap_F: 100nF; AEC Category: Q200
C37 C122 C196 = CMP-0008017-2: CAP, CERM, 10 uF, 10 V, +/- 10%, X7R, 0805; Manufacturer: MuRata; TaMin_C: -55°C; Polarized: N; SizeAreaWB_mm2: 6.75; Value1: Unknown; U/M: EA; Value: 10uF; TaMax_C: 125°C; SizeZ_mm: 1.45; SizeX_mm: 2; SizeY_mm: 1.25; Cap_Case: 0805; Value2: 10V; SizeArea_mm2: 2.5; CompType: Capacitor; Cap_F: 10µF; AEC Category: Q200
C55 = CMP-0006669-2: CAP, CERM, 0.047 uF, 25 V, +/- 10%, X7R, 0402; Manufacturer: MuRata; TaMin_C: -55°C; Polarized: N; SizeAreaWB_mm2: 3; Value1: Unknown; U/M: EA; TaMax_C: 125°C; SizeZ_mm: 0.6; SizeX_mm: 1; SizeY_mm: 0.5; Cap_Case: 0402; Value2: 25V; Cap_F: 47nF; AEC Category: Q200
C95 C121 = CMP-0860920-1: as C30 on sheet PROC196A_Ethernet_PHY
C147 C171 = CMP-0007134-5: CAP, CERM, 2.2 uF, 6.3 V, +/- 10%, X7R, AEC-Q200 Grade 1, 0603; Manufacturer: MuRata; TaMin_C: -55°C; Polarized: N; SizeAreaWB_mm2: 4.68; Value1: Unknown; U/M: EA; Value: 2.2uF; TaMax_C: 125°C; SizeZ_mm: 1; SizeX_mm: 1.6; SizeY_mm: 0.8; Cap_Case: 0603; Value2: 6.3V; SizeArea_mm2: 1.28; AEC Qualified: Y; Cap_F: 2.2µF; AEC Category: Q200
C148 C178 = CMP-0006350-2: CAP, CERM, 0.1 uF, 10 V, +/- 10%, X7R, AEC-Q200 Grade 1, 0402; Manufacturer: MuRata; TaMin_C: -55°C; Polarized: N; SizeAreaWB_mm2: 3; Value1: Unknown; U/M: EA; Value: 0.1uF; TaMax_C: 125°C; SizeZ_mm: 0.6; SizeX_mm: 1; SizeY_mm: 0.5; Cap_Case: 0402; Value2: 10V; AEC Qualified: Y; Cap_F: 100nF; AEC Category: Q200
C197 = CMP-0860898-1: CAP, CERM, 10 µF, 50 V,+/- 10%, X7R, AEC-Q200 Grade 1, 1206; Manufacturer: TDK; SizeY_mm: 1.6; AEC Category: Q200; U/M: EA; Polarized: N; VDC_V: 50V; TaMin_C: -55°C; TaMax_C: 125°C; SizeX_mm: 3.2; AEC Qualified: Y; SizeZ_mm: 1.35; Value: 10uF; SizeArea_mm2: 5.12; Cap_Case: 1206; SizeAreaWB_mm2: 10.92; AEC Grade: 1
D10 = CMP-0002839-2: LED, Yellow, SMD; Manufacturer: Rohm; Vf_V: 2.1V; Tjmax_C: 85°C; Value1: W; Type: InGaN; Io_A: 20mA
D14 = CMP-0002841-1: LED, Orange, SMD; Manufacturer: Rohm; Io_A: 20mA; Tjmax_C: 85°C; Value1: W; U/M: EA; Vf_V: 2.1V; Type: InGaN
FB1 = CMP-0003348-2: Ferrite Bead, 1000 ohm @ 100 MHz, 0.6 A, 0603; Manufacturer: MuRata; Ztyp@1GHz_Ohm: 1k; SizeAreaWB_mm2: 4.68; DCR_ohm: 3.5d; Value1: 0.35 ohm; Imax_A: 6dA; SizeZ_mm: 1; SizeX_mm: 1.6; SizeY_mm: 0.8; Value2: 0.6A; SizeArea_mm2: 1.28
FB2 R48 = CMP-0089848-1: 600 Ohms @ 100MHz 1 Power Line Ferrite Bead 0603 (1608 Metric) 1.3A 150mOhm; Manufacturer: Murata; Tolerance_%: 25%; SizeZ_mm: 0.95mm; Impedance At Frequency: 600Ω @ 100MHz; AEC Qualified: Yes; AEC Grade: Grade 1; DCR_ohm: 1.5d
R28 = CMP-0023343-3: RES, 0, 1%, 0.1 W, AEC-Q200 Grade 0, 0603; Manufacturer: Stackpole Electronics Inc; Power_W: 100mW; TempCo: ppm/C; U/M: EA; Value: 0; SizeX_mm: 1.6; SizeY_mm: 0.8; SizeZ_mm: 1; Value2: 0.1W; SizeArea_mm2: 1.28; AEC Qualified: Y; AEC Category: Q200
R34 = CMP-0026890-5: as R340 on sheet PROC196A_Ethernet_PHY
R46 R350 = CMP-0025958-3: RES, 10.0 k, 1%, 0.063 W, AEC-Q200 Grade 0, 0402; Manufacturer: Vishay-Dale; Power_W: 63mW; TempCo: 100 ppm/C; Value_Code: 10k0; Value: 10.0k; EIA_Code: E96; Res_ohm: 10k; SizeX_mm: 1; SizeY_mm: 0.5; SizeZ_mm: 0.6; Value2: 0.063W; CompType: Resistor; AEC Qualified: Y; VDC_V: 50V; AEC Category: Q200; AEC Grade: 0
R50 R51 R246 R259 R367 = CMP-0026992-3: RES, 0, 5%, 0.1 W, AEC-Q200 Grade 0, 0402; Manufacturer: Panasonic; Power_W: 100mW; TempCo: 600 ppm/C; Value_Code: 0000; Value: 0; EIA_Code: E24; SizeX_mm: 1; SizeY_mm: 0.5; SizeZ_mm: 0.6; Value2: 0.1W; AEC Qualified: Y; VDC_V: 50V; AEC Category: Q200; SizeAreaWB_mm2: 3
R74 R96 R100 R178 R225 R230 R234 R237-R240 R245 R247 R249 = CMP-0089575-2: as R98 on sheet PROC196A_Ethernet_PHY
R77 R93 = CMP-0026699-1: as R108 on sheet PROC196A_Ethernet_PHY
R79 R89 R252-R258 = CMP-0026237-2: as R92 on sheet PROC196A_Ethernet_PHY
R242 = CMP-0026993-2: RES, 100, 5%, 0.1 W, AEC-Q200 Grade 0, 0402; Manufacturer: Panasonic; Power_W: 100mW; TempCo: 200 ppm/C; Value_Code: 100R; U/M: EA; Value: 100; EIA_Code: E24; SizeX_mm: 1; SizeY_mm: 0.5; SizeZ_mm: 0.6; Value2: 0.1W; AEC Qualified: Y; AEC Grade: 0; AEC Category: Q200
R248 = CMP-0022138-4: RES, 1.00 M, 1%, 0.1 W, AEC-Q200 Grade 0, 0603; Manufacturer: Vishay-Dale; Power_W: 100mW; TempCo: 100 ppm/C; Value_Code: 1M00; Value: 1.00Meg; EIA_Code: E96; Res_ohm: 1M; SizeX_mm: 1.6; SizeY_mm: 0.8; SizeZ_mm: 1; Value2: 0.1W; SizeArea_mm2: 1.28; AEC Qualified: Y; VDC_V: 75V; AEC Category: Q200; AEC Grade: 0
R250 R251 R314 = CMP-0025958-3: RES, 10.0 k, 1%, 0.063 W, AEC-Q200 Grade 0, 0402; Manufacturer: Vishay-Dale; Power_W: 63mW; TempCo: 100 ppm/C; Value_Code: 10k0; Value: 10.0k; EIA_Code: E96; Res_ohm: 10k; SizeX_mm: 1; SizeY_mm: 0.5; SizeZ_mm: 0.6; Value2: 0.063W; AEC Qualified: Y; VDC_V: 50V; AEC Category: Q200; AEC Grade: 0
TP2 TP3 = CMP-0078143-3: TEST POINT.  No entry in BOM.
U4 = CMP-0085268-1: Low Power Auto PHY 1000BASE-T1 Automotive Ethernet Physical Layer Transceiver, RND0036A (VQFNP-36); Manufacturer: Texas Instruments; Alternate PartNumber: DP83TG720SWRNDTQ1; SizeZ_mm: 0.9; AEC Qualified: Y; AEC Category: Q200; CompType: IC; SizeArea_mm2: 36; SizeAreaWB_mm2: 64; SizeX_mm: 6
U33 = CMP-0860463-1: Automotive 150-mA high-voltage ultra-low-IQ low-dropout (LDO) linear regulator, DRV0006A (WSON-6); Alternate Manufacturer: Texas Instruments; AEC Qualified: Y; SizeY_mm: 2; SizeZ_mm: 0.8; AEC Category: Q200; CompType: IC; SizeArea_mm2: 4; SizeAreaWB_mm2: 9
Y5 = CMP-0004614-3: Crystal, 25 MHz, 18 pF, SMD; Manufacturer: Abracon Corporation; TaMax_C: 85°C; TaMin_C: -40°C; Frequency Stability: +/-25ppm; Frequency_Fixed: 25MHz

## Sheet PROC196A_Auto_Ethernet_conn.SchDoc
size 431 x 279 mm; Date: Not shown in title block; ApprovedBy: Not shown in title block; CheckedBy: Not shown in title block; Author: Not shown in title block; CompanyName: Not shown in title block; Engineer: Not shown in title block; Organization: Not shown in title block; Address1: Not shown in title block; Address2: Not shown in title block; Address3: Not shown in title block; Address4: Not shown in title block; DocumentNumber: 15; Revision: Use project parameter SCH_Rev; SheetNumber: 15; SheetTotal: 25; PageSetup: Record=PageOptions¦CenterHorizontal=True¦CenterVertical=True¦PrintScale=1.00¦XCorrection=1.00¦YCorrection=1.00¦PrintKind=0¦BorderSize=5000000¦LeftOffset=0¦BottomOffset=0¦Orientation=2¦PaperLength=1000¦PaperWidth=1000¦Scale=100¦PaperSource=15¦PrintQuality=600¦MediaType=1¦DitherType=10¦PaperKind=Letter¦PrintScaleMode=1
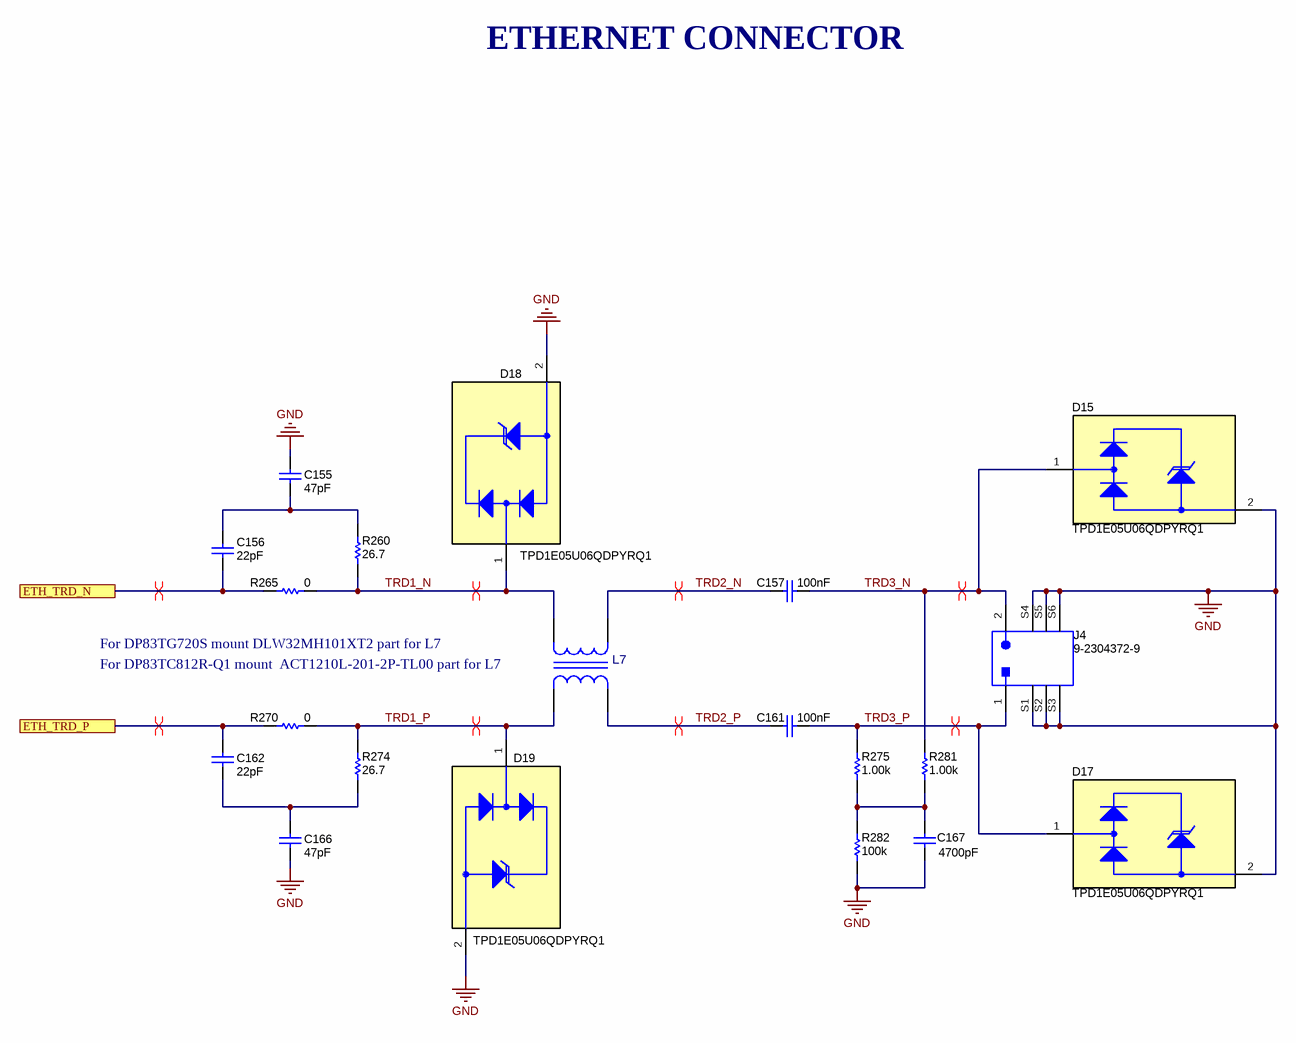
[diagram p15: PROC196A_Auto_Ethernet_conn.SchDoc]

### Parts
C155  ValueDisplayed: 47pF  [0402L]  (hidden comment: GRM1555C1H470FA01D)
C156  ValueDisplayed: 22pF  [0402L]  (hidden comment: GRM1555C1H220FA01D)
C157  Cap_F: 100nF  [0805_HV]  (hidden comment: CGA4J2X7R2A104K125AA)
C161  Cap_F: 100nF  [0805_HV]  (hidden comment: CGA4J2X7R2A104K125AA)
C162  ValueDisplayed: 22pF  [0402L]  (hidden comment: GRM1555C1H220FA01D)
C166  ValueDisplayed: 47pF  [0402L]  (hidden comment: GRM1555C1H470FA01D)
C167  ValueDisplayed: 4700pF  [1206L]  (hidden comment: GRM31BR73A472KW01L)
D15  TPD1E05U06QDPYRQ1  [DPY0002A]
D17  TPD1E05U06QDPYRQ1  [DPY0002A]
D18  TPD1E05U06QDPYRQ1  [DPY0002A]
D19  TPD1E05U06QDPYRQ1  [DPY0002A]
J4  9-2304372-9  [TE_9-2304372-9]
L7  ACT1210L-201-2P-TL00  [FP-ACT1210L-201-2P-TL00_SMD4-MFG]  (value not drawn)
R260  ValueDisplayed: 26.7  [0402L]  (hidden comment: CRCW040226R7FKED)
R265  ValueDisplayed: 0  [0402L]  (hidden comment: CRCW04020000Z0EDHP)
R270  ValueDisplayed: 0  [0402L]  (hidden comment: CRCW04020000Z0EDHP)
R274  ValueDisplayed: 26.7  [0402L]  (hidden comment: CRCW040226R7FKED)
R275  ValueDisplayed: 1.00k  [0805L]  (hidden comment: ERJ-P06F1001V)
R281  ValueDisplayed: 1.00k  [0805L]  (hidden comment: ERJ-P06F1001V)
R282  ValueDisplayed: 100k  [0805_HV]  (hidden comment: CRCW0805100KJNEA)

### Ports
ETH_TRD_N, ETH_TRD_P

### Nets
GND: C155.1 C166.2 C167.2 D15.2(GND) D17.2(GND) D18.2(GND) D19.2(GND) J4.S1(GND) J4.S2(GND) J4.S3(GND) J4.S4(GND) J4.S5(GND) J4.S6(GND) R282.1
ETH_TRD_N: C156.2 R265.1 ; port ETH_TRD_N
ETH_TRD_P: C162.1 R270.1 ; port ETH_TRD_P
TRD1_N: D18.1(I/O) L7.1 R260.1 R265.2
TRD1_P: D19.1(I/O) L7.2 R270.2 R274.2
TRD2_N: C157.2 L7.4
TRD2_P: C161.2 L7.3
TRD3_N: C157.1 D15.1(I/O) J4.2 R281.2
TRD3_P: C161.1 D17.1(I/O) J4.1 R275.2
NetC155_2: C155.2 C156.1 R260.2
NetC162_2: C162.2 C166.1 R274.1
NetC167_1: C167.1 R275.1 R281.1 R282.2

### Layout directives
differential pair: ETH_TRD_N, ETH_TRD_P, TRD1_N, TRD1_P, TRD2_N, TRD2_P, TRD3_N, TRD3_P

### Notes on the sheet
- ETHERNET CONNECTOR
- For DP83TG720S mount DLW32MH101XT2 part for L7
- For DP83TC812R-Q1 mount  ACT1210L-201-2P-TL00 part for L7

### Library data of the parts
C155 C166 = CMP-0006467-2: CAP, CERM, 47 pF, 50 V, +/- 1%, C0G/NP0, 0402; Manufacturer: MuRata; TaMin_C: -55°C; Polarized: N; SizeAreaWB_mm2: 3; Value1: Unknown; U/M: EA; Value: 47pF; TaMax_C: 125°C; SizeZ_mm: 0.6; SizeX_mm: 1; SizeY_mm: 0.5; Cap_Case: 0402; Value2: 50V; CompType: Capacitor; AEC Category: Q200
C156 C162 = CMP-0006438-2: CAP, CERM, 22 pF, 50 V, +/- 1%, C0G/NP0, 0402; Manufacturer: MuRata; TaMin_C: -55°C; Polarized: N; SizeAreaWB_mm2: 3; Value1: Unknown; U/M: EA; Value: 22pF; TaMax_C: 125°C; SizeZ_mm: 0.6; SizeX_mm: 1; SizeY_mm: 0.5; Cap_Case: 0402; Value2: 50V; CompType: Capacitor; AEC Category: Q200
C157 C161 = CMP-0007969-2: CAP, CERM, 0.1 uF, 100 V, +/- 10%, X7R, AEC-Q200 Grade 1, 0805; Manufacturer: TDK; TaMin_C: -55°C; ESR_ohm: 0.020726; Polarized: N; SizeAreaWB_mm2: 6.75; Value1: 0.020726 ohm; U/M: EA; Value: 0.1uF; TaMax_C: 125°C; SizeZ_mm: 1.45; SizeX_mm: 2; SizeY_mm: 1.25; Cap_Case: 0805; Value2: 100V; SizeArea_mm2: 2.5; AEC Qualified: Y; IRMS_A: 1.456A; AEC Grade: 1; AEC Category: Q200
C167 = CMP-0008920-2: CAP, CERM, 4700 pF, 1000 V, +/- 10%, X7R, 1206; Manufacturer: MuRata; TaMin_C: -55°C; Polarized: N; SizeAreaWB_mm2: 10.92; Value1: Unknown; U/M: EA; Value: 4700pF; TaMax_C: 125°C; SizeZ_mm: 1.35; SizeX_mm: 3.2; SizeY_mm: 1.6; Cap_Case: 1206; Value2: 1000V; SizeArea_mm2: 5.12; Cap_F: 4.7nF; VDC_V: 1kV; AEC Category: Q200
D15 D17-D19 = CMP-0073591-4: Automotive 1-Channel Ultra-Low-Capacitance IEC ESD Protection Diode, DPY0002A (X1SON-2); Alternate Manufacturer: Texas Instruments; Alternate PartNumber: TPD1E05U06QDPYTQ1; SizeZ_mm: 0.45; SizeAreaWB_mm2: 3.2; SizeArea_mm2: 0.6; CompType: IC; AEC Category: Q200; AEC Qualified: Y; SizeX_mm: 1.0
J4 = CMP-0078655-1: 1 Port Header Assembly, TH; Manufacturer: TE Connectivity; Gender: Male; CompType: Connector; Shrouded: Y
L7 = CMP-0089334-1: 200µH @ 100kHz 2 Line Common Mode Choke Surface Mount 70mA DCR 5.5Ohm; Manufacturer: TDK; Impedance At Frequency: 9.5kΩ @ 10MHz; Tolerance_%: -10/30%; SizeZ_mm: 2.5mm; DCR_ohm: 5.5; AEC Qualified: Yes; AEC Grade: Grade 1
R260 = CMP-0026210-2: RES, 26.7, 1%, 0.063 W, AEC-Q200 Grade 0, 0402; Manufacturer: Vishay-Dale; Power_W: 63mW; TempCo: 100 ppm/C; Value_Code: 26R7; Value: 26.7; SizeX_mm: 1; SizeY_mm: 0.5; SizeZ_mm: 0.6; Value2: 0.063W; AEC Qualified: Y; VDC_V: 50V; AEC Grade: 0; AEC Category: Q200; EIA_Code: E96
R265 R270 = CMP-0081856-1: RES, 0, 0%, 0.2 W, AEC-Q200 Grade 0, 0402; Manufacturer: Vishay-Dale; SizeAreaWB_mm2: 3; SizeArea_mm2: 0.5; AEC Qualified: Y; AEC Category: Q200; Value: 0; SizeZ_mm: 0.6; Power_W: 200mW; VDC_V: 50V; Value2: 0.2W; SizeX_mm: 1
R274 = CMP-0026210-2: RES, 26.7, 1%, 0.063 W, AEC-Q200 Grade 0, 0402; Manufacturer: Vishay-Dale; Power_W: 63mW; TempCo: 100 ppm/C; Value_Code: 26R7; Value: 26.7; SizeX_mm: 1; SizeY_mm: 0.5; SizeZ_mm: 0.6; Value2: 0.063W; CompType: Resistor; AEC Qualified: Y; VDC_V: 50V; AEC Grade: 0; AEC Category: Q200; EIA_Code: E96
R275 R281 = CMP-0021848-2: RES, 1.00 k, 1%, 0.25 W, 0805; Manufacturer: Panasonic; Power_W: 250mW; TempCo: 100 ppm/C; Value_Code: 1k00; U/M: EA; Value: 1.00k; EIA_Code: E96; Res_ohm: 1k; SizeX_mm: 2; SizeY_mm: 1.25; SizeZ_mm: 1.45; Value2: 0.25W; SizeArea_mm2: 2.5; VDC_V: 400V; AEC Category: Q200
R282 = CMP-0020444-3: RES, 100 k, 5%, 0.125 W, AEC-Q200 Grade 0, 0805; Manufacturer: Vishay-Dale; Power_W: 125mW; TempCo: 200 ppm/C; Value: 100k; EIA_Code: E24; SizeX_mm: 2; SizeY_mm: 1.25; SizeZ_mm: 1.45; Value2: 0.125W; SizeArea_mm2: 2.5; AEC Qualified: Y; VDC_V: 150V; AEC Category: Q200; AEC Grade: 0

## Sheet PROC196A_FTDI_PWR.SchDoc
size 431 x 279 mm; Date: Not shown in title block; ApprovedBy: Not shown in title block; CheckedBy: Not shown in title block; Author: Not shown in title block; CompanyName: Not shown in title block; Engineer: Not shown in title block; Organization: Not shown in title block; Address1: Not shown in title block; Address2: Not shown in title block; Address3: Not shown in title block; Address4: Not shown in title block; DocumentNumber: 16; Revision: Use project parameter SCH_Rev; SheetNumber: 16; SheetTotal: 25; PageSetup: Record=PageOptions¦CenterHorizontal=True¦CenterVertical=True¦PrintScale=1.00¦XCorrection=1.00¦YCorrection=1.00¦PrintKind=0¦BorderSize=5000000¦LeftOffset=0¦BottomOffset=0¦Orientation=2¦PaperLength=1000¦PaperWidth=1000¦Scale=100¦PaperSource=15¦PrintQuality=600¦MediaType=1¦DitherType=10¦PaperKind=Letter¦PrintScaleMode=1
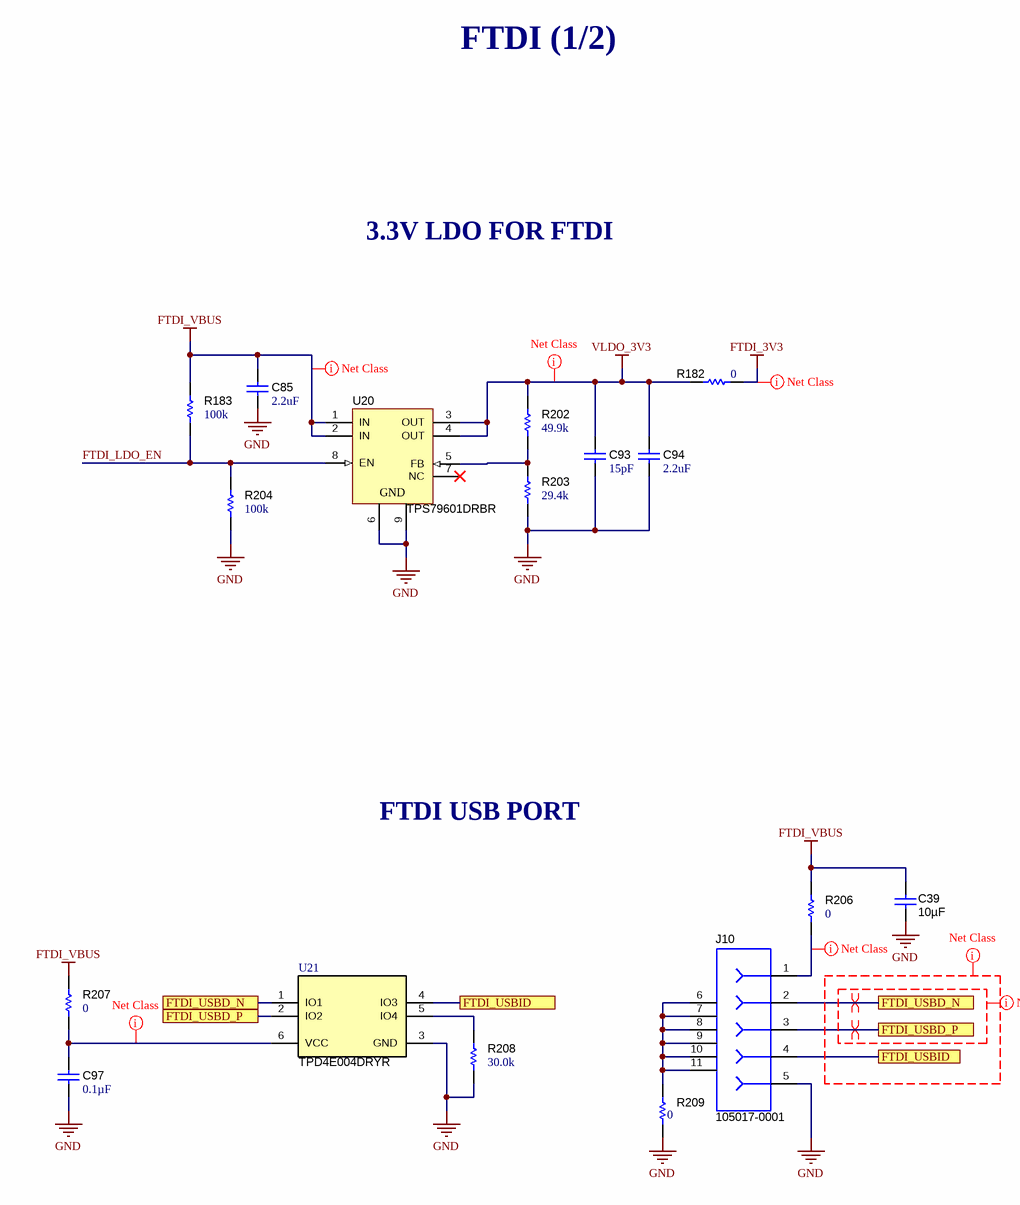
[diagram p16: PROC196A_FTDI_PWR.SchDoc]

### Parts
C39  Cap_F: 10µF  [0805L]  (hidden comment: CL21B106KOQNNNE)
C85  ValueDisplayed: 2.2uF  [0402_065L]  (hidden comment: C1005X7S1A225K050BC)
C93  ValueDisplayed: 15pF  [0402L]  (hidden comment: 04025A150FAT2A)
C94  ValueDisplayed: 2.2uF  [0402_065L]  (hidden comment: C1005X7S1A225K050BC)
C97  ValueDisplayed: 0.1µF  [0402L]  (hidden comment: C0402C104K8RACTU)
J10  105017-0001  [CONN_105017-0001]
R182  ValueDisplayed: 0  [0805L]  (hidden comment: CRCW08050000Z0EA)
R183  ValueDisplayed: 100k  [0402L]  (hidden comment: CRCW0402100KFKED)
R202  ValueDisplayed: 49.9k  [0402L]  (hidden comment: CRCW040249K9FKED)
R203  ValueDisplayed: 29.4k  [0402L]  (hidden comment: CRCW040229K4FKED)
R204  ValueDisplayed: 100k  [0402L]  (hidden comment: CRCW0402100KFKED)
R206  ValueDisplayed: 0  [0805L]  (hidden comment: CRCW08050000Z0EA)
R207  ValueDisplayed: 0  [0805L]  (hidden comment: CRCW08050000Z0EA)
R208  ValueDisplayed: 30.0k  [0402L]  (hidden comment: CRCW040230K0FKED)
R209  ValueDisplayed: 0  [0402L]  (hidden comment: ERJ-2GE0R00X)
U20  TPS79601DRBR  [DRB0008B]
U21  TPD4E004DRYR  [DRY0006A]

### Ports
FTDI_USBD_N, FTDI_USBD_P, FTDI_USBID

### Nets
FTDI_3V3: R182.2
FTDI_VBUS: C39.1 C85.1 R183.2 R206.2 R207.2 U20.1(IN) U20.2(IN)
GND: C39.2 C85.2 C93.2 C94.2 C97.2 J10.5 R203.2 R204.1 R208.1 R209.1 U20.6(GND) U20.9(GND) U21.3(GND)
VLDO_3V3: C93.1 C94.1 R182.1 R202.2 U20.3(OUT) U20.4(OUT)
FTDI_LDO_EN: R183.1 R204.2 U20.8(EN)
FTDI_USBD_N: J10.2 U21.1(IO1) ; port FTDI_USBD_N
FTDI_USBD_P: J10.3 U21.2(IO2) ; port FTDI_USBD_P
FTDI_USBID: J10.4 U21.4(IO3) ; port FTDI_USBID
NetC97_1: C97.1 R207.1 U21.6(VCC)
NetJ10_1: J10.1 R206.1
NetJ10_6: J10.6 J10.7 J10.8 J10.9 J10.10 J10.11 R209.2
NetR202_1: R202.1 R203.1 U20.5(FB)
NetR208_2: R208.2 U21.5(IO4)

Not connected (* = marked no-connect by the designer): U20 7(NC)*

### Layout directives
net class FTDI_USB: (no net found under the mark)
net class PWR: FTDI_3V3, FTDI_VBUS, NetC97_1, NetJ10_1, VLDO_3V3
differential pair: FTDI_USBD_N, FTDI_USBD_P
net class USB_DIFF: (no net found under the mark)

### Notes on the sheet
- FTDI (1/2)
- 3.3V LDO FOR FTDI
- FTDI USB PORT

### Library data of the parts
C39 = CMP-0007995-2: CAP, CERM, 10 uF, 16 V, +/- 10%, X7R, 0805; Manufacturer: Samsung Electro-Mechanics; TaMin_C: -55°C; Polarized: N; SizeAreaWB_mm2: 6.75; Value1: Unknown; U/M: EA; Value: 10uF; TaMax_C: 125°C; SizeZ_mm: 1.45; SizeX_mm: 2; SizeY_mm: 1.25; Cap_Case: 0805; Value2: 16V; SizeArea_mm2: 2.5; AEC Category: Q200
C85 C94 = CMP-0006302-2: CAP, CERM, 2.2 uF, 10 V, +/- 10%, X7S, 0402; Manufacturer: TDK; TaMin_C: -55°C; ESR_ohm: 5.925m; Polarized: N; SizeAreaWB_mm2: 3; Value1: 0.005925 ohm; U/M: EA; Value: 2.2uF; TaMax_C: 125°C; SizeZ_mm: 0.65; SizeX_mm: 1; SizeY_mm: 0.5; Cap_Case: 0402_065; Value2: 10V; CompType: Capacitor; Cap_F: 2.2µF; IRMS_A: 2.05591A; AEC Category: Q200
C93 = CMP-0078217-1: CAP, CERM, 15 pF, 50 V,+/- 1%, C0G/NP0, 0402; Manufacturer: AVX; TaMin_C: -55°C; Polarized: N; Green_Lifecycle: Not Set; SizeAreaWB_mm2: 3; Green_REACh: Incomplete; U/M: EA; Value: 15pF; TaMax_C: 125°C; SizeZ_mm: 0.6; SizeX_mm: 1; SizeY_mm: 0.5; Cap_Case: 0402; Value2: 50V; AEC Category: Q200
C97 = CMP-0078241-1: CAP, CERM, 0.1 µF, 10 V,+/- 10%, X7R, 0402; Manufacturer: Kemet; TaMin_C: -55°C; Polarized: N; SizeAreaWB_mm2: 3; U/M: EA; Value: 0.1uF; TaMax_C: 125°C; SizeZ_mm: 0.6; SizeX_mm: 1; SizeY_mm: 0.5; Cap_Case: 0402; Value2: 10V; Cap_F: 100nF; AEC Category: Q200
J10 = CMP-0055293-1: Connector, Receptacle, Micro-USB Type B, R/A, Bottom Mount SMT; Manufacturer: Molex; CNHeader: FALSE; Green_Lifecycle: Active; Gender: Female; Green_REACh: Passed; CompType: USB; CT: TRUE
R182 R206 R207 = CMP-0020442-3: RES, 0, 5%, 0.125 W, AEC-Q200 Grade 0, 0805; Manufacturer: Vishay-Dale; Power_W: 125mW; TempCo: 200 ppm/C; Value_Code: 0000; Value: 0; EIA_Code: E24; SizeX_mm: 2; SizeY_mm: 1.25; SizeZ_mm: 1.45; Value2: 0.125W; SizeArea_mm2: 2.5; AEC Qualified: Y; VDC_V: 150V; AEC Category: Q200
R183 = CMP-0025950-3: RES, 100 k, 1%, 0.063 W, AEC-Q200 Grade 0, 0402; Manufacturer: Vishay-Dale; Power_W: 63mW; TempCo: 100 ppm/C; Value: 100k; EIA_Code: E96; SizeX_mm: 1; SizeY_mm: 0.5; SizeZ_mm: 0.6; Value2: 0.063W; CompType: Resistor; AEC Qualified: Y; VDC_V: 50V; AEC Category: Q200; AEC Grade: 0; INSTALLATION: DNP
R202 = CMP-0026403-2: RES, 49.9 k, 1%, 0.063 W, AEC-Q200 Grade 0, 0402; Manufacturer: Vishay-Dale; Power_W: 63mW; TempCo: 100 ppm/C; Value_Code: 49k9; Value: 49.9k; EIA_Code: E96; SizeX_mm: 1; SizeY_mm: 0.5; SizeZ_mm: 0.6; Value2: 0.063W; AEC Qualified: Y; VDC_V: 50V; AEC Category: Q200; AEC Grade: 0
R203 = CMP-0026225-2: RES, 29.4 k, 1%, 0.063 W, AEC-Q200 Grade 0, 0402; Manufacturer: Vishay-Dale; Power_W: 63mW; TempCo: 100 ppm/C; Value_Code: 29k4; Value: 29.4k; EIA_Code: E96; SizeX_mm: 1; SizeY_mm: 0.5; SizeZ_mm: 0.6; Value2: 0.063W; AEC Qualified: Y; VDC_V: 50V; AEC Category: Q200; AEC Grade: 0
R204 = CMP-0025950-3: RES, 100 k, 1%, 0.063 W, AEC-Q200 Grade 0, 0402; Manufacturer: Vishay-Dale; Power_W: 63mW; TempCo: 100 ppm/C; Value: 100k; EIA_Code: E96; SizeX_mm: 1; SizeY_mm: 0.5; SizeZ_mm: 0.6; Value2: 0.063W; AEC Qualified: Y; VDC_V: 50V; AEC Category: Q200; AEC Grade: 0
R208 = CMP-0078244-2: RES, 30.0 k, 1%, 0.063 W, AEC-Q200 Grade 0, 0402; Manufacturer: Vishay-Dale; Power_W: 63mW; Green_Lifecycle: Active; TempCo: 100 ppm/C; Value_Code: 30k0; Green_REACh: Passed; Value: 30.0k; Res_ohm: 30k; SizeX_mm: 1; SizeY_mm: 0.5; SizeZ_mm: 0.6; Value2: 0.063W; AEC Qualified: Y; VDC_V: 50V; AEC Grade: 0; AEC Category: Q200
R209 = CMP-0026992-3: as R50 on sheet PROC196A_Auto_Ethernet_PHY
U20 = CMP-0036402-3: Single Output High PSRR LDO, 1 A, Adjustable 1.2 to 5.5 V Output, 2.7 to 5.5 V Input, 8-pin SON (DRB), -40 to 125 degC, Green (RoHS & no Sb/Br); Manufacturer: Texas Instruments; Vin(Min)(V): 2.7; Vout Adj(Max)(V): 5.5; Vout Adj(Min)(V): 1.2; Accuracy(%): 2; SubFamily: Single Channel LDO; Iq(Typ)(mA): 0.26; Vdo(Typ)(mV): 250; Iout(Max)(A): 1; AEC Category: Q200; AEC Qualified: N; CompType: IC; SizeAreaWB_mm2: 16.0; SizeArea_mm2: 9.0; SizeX_mm: 3.0; SizeZ_mm: 1.0
U21 = CMP-0043115-3: 4-Channel ESD Protection Array for High-Speed Data Interfaces, DRY0006A (USON-6); Manufacturer: Texas Instruments; IO Leakage Current(nA): 1; USB High Speed: TRUE; IO Capacitance(Typ)(pF): 1.6; Eco-Plan: Green (RoHS & no Sb/Br); IEC 61000-4-2 Contact(+/- kV): 8; Breakdown Voltage(Min)(V): 6; IEC 61000-4-2 Air-Gap(+/- kV): 12; AEC Category: Q200; AEC Qualified: N; CompType: IC; SizeAreaWB_mm2: 4.9; SizeArea_mm2: 1.45; SizeX_mm: 1.0; SizeZ_mm: 0.6; Rating: Catalog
